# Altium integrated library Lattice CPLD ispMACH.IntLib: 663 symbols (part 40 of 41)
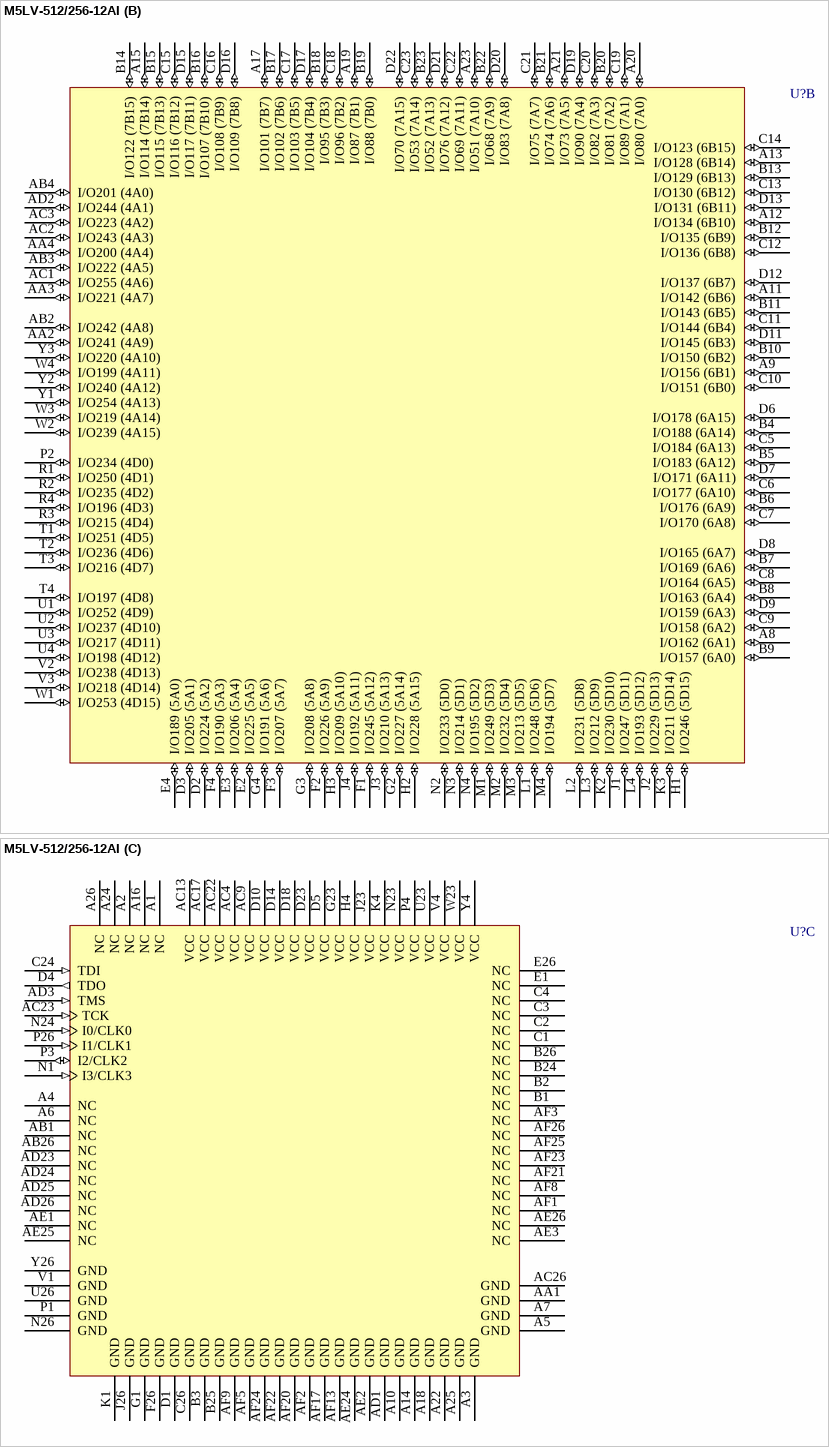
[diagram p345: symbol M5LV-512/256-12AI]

## M5LV-512/256-12AI
designator U?
High-Density and High-I/O Complex PLD
footprint SBGA352 (BGA, 352-Leads, Body 35x35mm, Pitch 1.27mm)
3D model M5LV-SBGA352 (352-Ball Super Ball Grid Array (SBGA352))
part A pins: AA23 I/O65 (1A3) (io), AA24 I/O48 (1A7) (io), AA25 I/O29 (1A9) (io), AA26 I/O10 (1A12) (io), AB23 I/O66 (1A0) (io), AB24 I/O49 (1A4) (io), AB25 I/O30 (1A5) (io), AC5 I/O185 (3A14) (io), AC6 I/O179 (3A10) (io), AC7 I/O172 (3A6) (io), AC8 I/O166 (3A2) (io), AC10 I/O152 (3B3) (io), AC11 I/O146 (3B7) (io), AC12 I/O138 (3B11) (io), AC14 I/O124 (2B11) (io), AC15 I/O118 (2B7) (io), AC16 I/O110 (2B3) (io), AC18 I/O97 (2A3) (io), AC19 I/O91 (2A7) (io), AC20 I/O84 (2A11) (io), AC21 I/O77 (2A15) (io), AC24 I/O50 (1A1) (io), AC25 I/O31 (1A2) (io), AD4 I/O202 (3A15) (io), AD5 I/O186 (3A11) (io), AD6 I/O180 (3A8) (io), AD7 I/O173 (3A4) (io), AD8 I/O167 (3A1) (io), AD9 I/O160 (3B1) (io), AD10 I/O153 (3B4) (io), AD11 I/O147 (3B8) (io), AD12 I/O139 (3B12) (io), AD13 I/O132 (2B15) (io), AD14 I/O125 (2B12) (io), AD15 I/O119 (2B8) (io), AD16 I/O111 (2B4) (io), AD17 I/O105 (2B0) (io), AD18 I/O98 (2A2) (io), AD19 I/O92 (2A5) (io), AD20 I/O85 (2A8) (io), AD21 I/O78 (2A10) (io), AD22 I/O71 (2A13) (io), AE4 I/O203 (3A13) (io), AE5 I/O187 (3A9) (io), AE6 I/O181 (3A7) (io), AE7 I/O174 (3A3) (io), AE8 I/O168 (3B0) (io), AE9 I/O161 (3B2) (io), AE10 I/O154 (3B5) (io), AE11 I/O148 (3B9) (io), AE12 I/O140 (3B13) (io), AE13 I/O133 (3B15) (io), AE14 I/O126 (2B13) (io), AE15 I/O120 (2B9) (io), AE16 I/O112 (2B5) (io), AE17 I/O106 (2B2) (io), AE18 I/O99 (2A0) (io), AE19 I/O93 (2A4) (io), AE20 I/O86 (2A6) (io), AE21 I/O79 (2A9) (io), AE22 I/O72 (2A12) (io), AE23 I/O67 (2A14) (io), AF4 I/O204 (3A12) (io), AF6 I/O182 (3A5) (io), AF7 I/O175 (3A0) (io), AF10 I/O155 (3B6) (io), AF11 I/O149 (3B10) (io), AF12 I/O141 (3B14) (io), AF14 I/O127 (2B14) (io), AF15 I/O121 (2B10) (io), AF16 I/O113 (2B6) (io), AF18 I/O100 (2B1) (io), AF19 I/O94 (2A1) (io), C25 I/O11 (0A1) (io), D24 I/O32 (0A2) (io), D25 I/O12 (0A3) (io), D26 I/O0 (0A6) (io), E23 I/O54 (0A0) (io), E24 I/O33 (0A5) (io), E25 I/O13 (0A8) (io), F23 I/O55 (0A4) (io), F24 I/O34 (0A7) (io), F25 I/O14 (0A9) (io), G24 I/O35 (0A10) (io), G25 I/O15 (0A12) (io), G26 I/O1 (0A13) (io), H23 I/O56 (0A11) (io), H24 I/O36 (0A14) (io), H25 I/O16 (0A15) (io), H26 I/O2 (0D15) (io), J24 I/O37 (0D14) (io), J25 I/O17 (0D13) (io), K23 I/O57 (0D12) (io), K24 I/O38 (0D11) (io), K25 I/O18 (0D10) (io), K26 I/O3 (0D9) (io), L23 I/O58 (0D8) (io), L24 I/O39 (0D7) (io), L25 I/O19 (0D6) (io), L26 I/O4 (0D5) (io), M23 I/O59 (0D3) (io), M24 I/O40 (0D4) (io), M25 I/O20 (0D2) (io), M26 I/O5 (0D1) (io), N25 I/O21 (0D0) (io), P23 I/O60 (1D2) (io), P24 I/O41 (1D1) (io), P25 I/O22 (1D0) (io), R23 I/O61 (1D7) (io), R24 I/O42 (1D5) (io), R25 I/O23 (1D4) (io), R26 I/O6 (1D3) (io), T23 I/O62 (1D12) (io), T24 I/O43 (1D9) (io), T25 I/O24 (1D8) (io), T26 I/O7 (1D6) (io), U24 I/O44 (1D14) (io), U25 I/O25 (1D10) (io), V23 I/O63 (1A11) (io), V24 I/O45 (1A13) (io), V25 I/O26 (1D13) (io), V26 I/O8 (1D11) (io), W24 I/O46 (1A10) (io), W25 I/O27 (1A15) (io), W26 I/O9 (1D15) (io), Y23 I/O64 (1A6) (io), Y24 I/O47 (1A8) (io), Y25 I/O28 (1A14) (io)
part B pins: A8 I/O162 (6A1) (io), A9 I/O156 (6B1) (io), A11 I/O142 (6B6) (io), A12 I/O134 (6B10) (io), A13 I/O128 (6B14) (io), A15 I/O114 (7B14) (io), A17 I/O101 (7B7) (io), A19 I/O87 (7B1) (io), A20 I/O80 (7A0) (io), A21 I/O73 (7A5) (io), A23 I/O51 (7A10) (io), AA2 I/O241 (4A9) (io), AA3 I/O221 (4A7) (io), AA4 I/O200 (4A4) (io), AB2 I/O242 (4A8) (io), AB3 I/O222 (4A5) (io), AB4 I/O201 (4A0) (io), AC1 I/O255 (4A6) (io), AC2 I/O243 (4A3) (io), AC3 I/O223 (4A2) (io), AD2 I/O244 (4A1) (io), B4 I/O188 (6A14) (io), B5 I/O183 (6A12) (io), B6 I/O176 (6A9) (io), B7 I/O169 (6A6) (io), B8 I/O163 (6A4) (io), B9 I/O157 (6A0) (io), B10 I/O150 (6B2) (io), B11 I/O143 (6B5) (io), B12 I/O135 (6B9) (io), B13 I/O129 (6B13) (io), B14 I/O122 (7B15) (io), B15 I/O115 (7B13) (io), B16 I/O107 (7B10) (io), B17 I/O102 (7B6) (io), B18 I/O95 (7B3) (io), B19 I/O88 (7B0) (io), B20 I/O81 (7A2) (io), B21 I/O74 (7A6) (io), B22 I/O68 (7A9) (io), B23 I/O52 (7A13) (io), C5 I/O184 (6A13) (io), C6 I/O177 (6A10) (io), C7 I/O170 (6A8) (io), C8 I/O164 (6A5) (io), C9 I/O158 (6A2) (io), C10 I/O151 (6B0) (io), C11 I/O144 (6B4) (io), C12 I/O136 (6B8) (io), C13 I/O130 (6B12) (io), C14 I/O123 (6B15) (io), C15 I/O116 (7B12) (io), C16 I/O108 (7B9) (io), C17 I/O103 (7B5) (io), C18 I/O96 (7B2) (io), C19 I/O89 (7A1) (io), C20 I/O82 (7A3) (io), C21 I/O75 (7A7) (io), C22 I/O69 (7A11) (io), C23 I/O53 (7A14) (io), D2 I/O224 (5A2) (io), D3 I/O205 (5A1) (io), D6 I/O178 (6A15) (io), D7 I/O171 (6A11) (io), D8 I/O165 (6A7) (io), D9 I/O159 (6A3) (io), D11 I/O145 (6B3) (io), D12 I/O137 (6B7) (io), D13 I/O131 (6B11) (io), D15 I/O117 (7B11) (io), D16 I/O109 (7B8) (io), D17 I/O104 (7B4) (io), D19 I/O90 (7A4) (io), D20 I/O83 (7A8) (io), D21 I/O76 (7A12) (io), D22 I/O70 (7A15) (io), E2 I/O225 (5A5) (io), E3 I/O206 (5A4) (io), E4 I/O189 (5A0) (io), F1 I/O245 (5A12) (io), F2 I/O226 (5A9) (io), F3 I/O207 (5A7) (io), F4 I/O190 (5A3) (io), G2 I/O227 (5A14) (io), G3 I/O208 (5A8) (io), G4 I/O191 (5A6) (io), H1 I/O246 (5D15) (io), H2 I/O228 (5A15) (io), H3 I/O209 (5A10) (io), J1 I/O247 (5D11) (io), J2 I/O229 (5D13) (io), J3 I/O210 (5A13) (io), J4 I/O192 (5A11) (io), K2 I/O230 (5D10) (io), K3 I/O211 (5D14) (io), L1 I/O248 (5D6) (io), L2 I/O231 (5D8) (io), L3 I/O212 (5D9) (io), L4 I/O193 (5D12) (io), M1 I/O249 (5D3) (io), M2 I/O232 (5D4) (io), M3 I/O213 (5D5) (io), M4 I/O194 (5D7) (io), N2 I/O233 (5D0) (io), N3 I/O214 (5D1) (io), N4 I/O195 (5D2) (io), P2 I/O234 (4D0) (io), R1 I/O250 (4D1) (io), R2 I/O235 (4D2) (io), R3 I/O215 (4D4) (io), R4 I/O196 (4D3) (io), T1 I/O251 (4D5) (io), T2 I/O236 (4D6) (io), T3 I/O216 (4D7) (io), T4 I/O197 (4D8) (io), U1 I/O252 (4D9) (io), U2 I/O237 (4D10) (io), U3 I/O217 (4D11) (io), U4 I/O198 (4D12) (io), V2 I/O238 (4D13) (io), V3 I/O218 (4D14) (io), W1 I/O253 (4D15) (io), W2 I/O239 (4A15) (io), W3 I/O219 (4A14) (io), W4 I/O199 (4A11) (io), Y1 I/O254 (4A13) (io), Y2 I/O240 (4A12) (io), Y3 I/O220 (4A10) (io)
part C pins: A1 NC, A2 NC, A3 GND (power), A4 NC, A5 GND (power), A6 NC, A7 GND (power), A10 GND (power), A14 GND (power), A16 NC, A18 GND (power), A22 GND (power), A24 NC, A25 GND (power), A26 NC, AA1 GND (power), AB1 NC, AB26 NC, AC4 VCC (power), AC9 VCC (power), AC13 VCC (power), AC17 VCC (power), AC22 VCC (power), AC23 TCK (in), AC26 GND (power), AD1 GND (power), AD3 TMS (in), AD23 NC, AD24 NC, AD25 NC, AD26 NC, AE1 NC, AE2 GND (power), AE3 NC, AE24 GND (power), AE25 NC, AE26 NC, AF1 NC, AF2 GND (power), AF3 NC, AF5 GND (power), AF8 NC, AF9 GND (power), AF13 GND (power), AF17 GND (power), AF20 GND (power), AF21 NC, AF22 GND (power), AF23 NC, AF24 GND (power), AF25 NC, AF26 NC, B1 NC, B2 NC, B3 GND (power), B24 NC, B25 GND (power), B26 NC, C1 NC, C2 NC, C3 NC, C4 NC, C24 TDI (in), C26 GND (power), D1 GND (power), D4 TDO (out), D5 VCC (power), D10 VCC (power), D14 VCC (power), D18 VCC (power), D23 VCC (power), E1 NC, E26 NC, F26 GND (power), G1 GND (power), G23 VCC (power), H4 VCC (power), J23 VCC (power), J26 GND (power), K1 GND (power), K4 VCC (power), N1 I3/CLK3 (in), N23 VCC (power), N24 I0/CLK0 (in), N26 GND (power), P1 GND (power), P3 I2/CLK2 (io), P4 VCC (power), P26 I1/CLK1 (in), U23 VCC (power), U26 GND (power), V1 GND (power), V4 VCC (power), W23 VCC (power), Y4 VCC (power), Y26 GND (power)

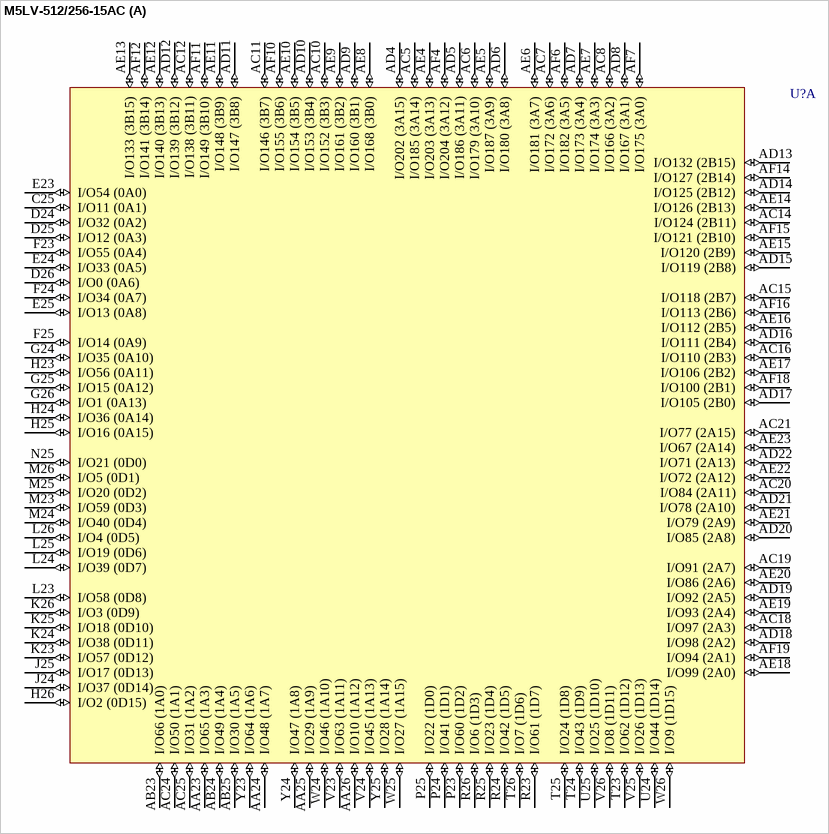
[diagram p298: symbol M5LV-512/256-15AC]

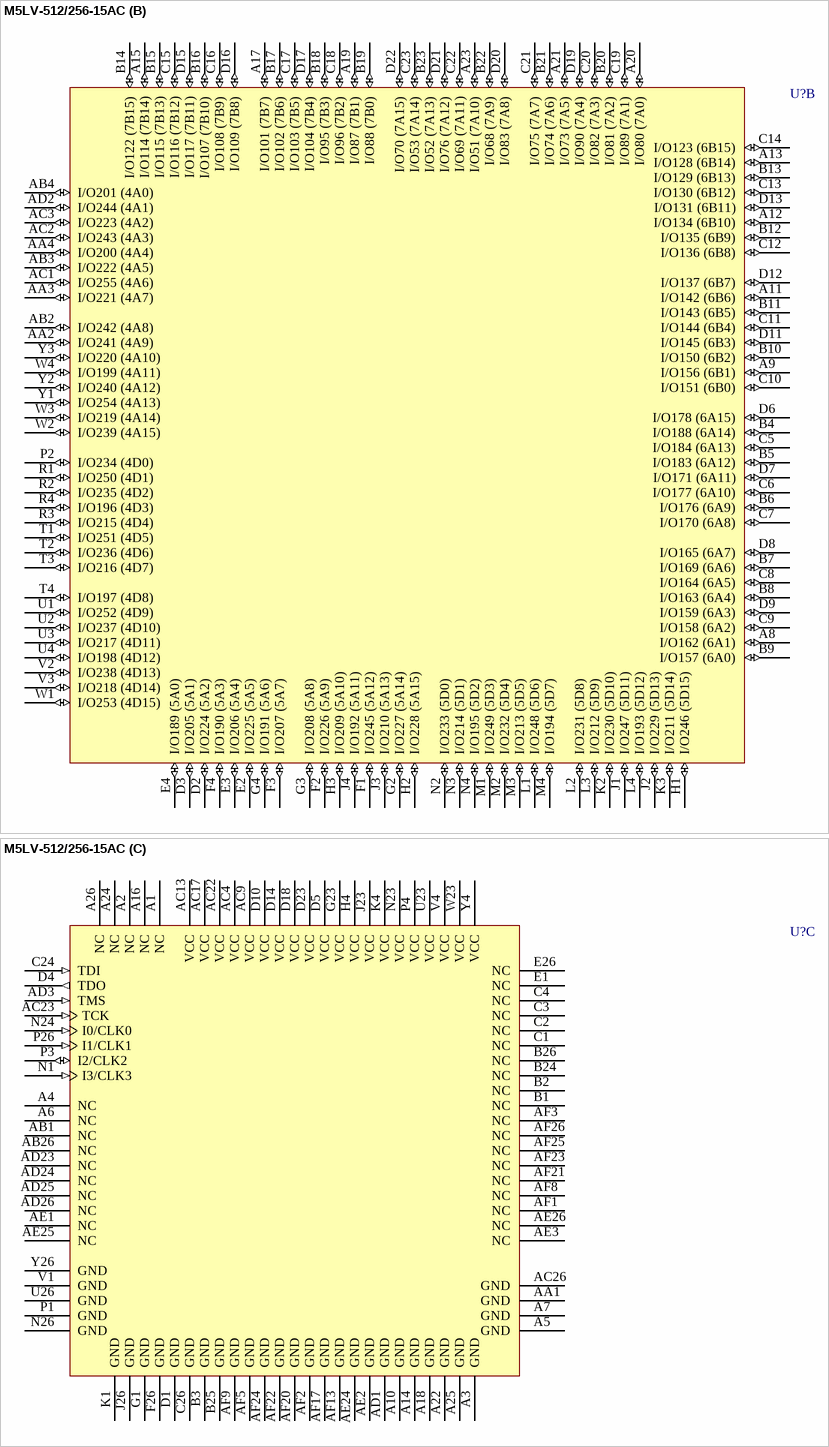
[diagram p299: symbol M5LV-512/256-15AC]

## M5LV-512/256-15AC
designator U?
High-Density and High-I/O Complex PLD
footprint SBGA352 (BGA, 352-Leads, Body 35x35mm, Pitch 1.27mm)
3D model M5LV-SBGA352 (352-Ball Super Ball Grid Array (SBGA352))
part A pins: AA23 I/O65 (1A3) (io), AA24 I/O48 (1A7) (io), AA25 I/O29 (1A9) (io), AA26 I/O10 (1A12) (io), AB23 I/O66 (1A0) (io), AB24 I/O49 (1A4) (io), AB25 I/O30 (1A5) (io), AC5 I/O185 (3A14) (io), AC6 I/O179 (3A10) (io), AC7 I/O172 (3A6) (io), AC8 I/O166 (3A2) (io), AC10 I/O152 (3B3) (io), AC11 I/O146 (3B7) (io), AC12 I/O138 (3B11) (io), AC14 I/O124 (2B11) (io), AC15 I/O118 (2B7) (io), AC16 I/O110 (2B3) (io), AC18 I/O97 (2A3) (io), AC19 I/O91 (2A7) (io), AC20 I/O84 (2A11) (io), AC21 I/O77 (2A15) (io), AC24 I/O50 (1A1) (io), AC25 I/O31 (1A2) (io), AD4 I/O202 (3A15) (io), AD5 I/O186 (3A11) (io), AD6 I/O180 (3A8) (io), AD7 I/O173 (3A4) (io), AD8 I/O167 (3A1) (io), AD9 I/O160 (3B1) (io), AD10 I/O153 (3B4) (io), AD11 I/O147 (3B8) (io), AD12 I/O139 (3B12) (io), AD13 I/O132 (2B15) (io), AD14 I/O125 (2B12) (io), AD15 I/O119 (2B8) (io), AD16 I/O111 (2B4) (io), AD17 I/O105 (2B0) (io), AD18 I/O98 (2A2) (io), AD19 I/O92 (2A5) (io), AD20 I/O85 (2A8) (io), AD21 I/O78 (2A10) (io), AD22 I/O71 (2A13) (io), AE4 I/O203 (3A13) (io), AE5 I/O187 (3A9) (io), AE6 I/O181 (3A7) (io), AE7 I/O174 (3A3) (io), AE8 I/O168 (3B0) (io), AE9 I/O161 (3B2) (io), AE10 I/O154 (3B5) (io), AE11 I/O148 (3B9) (io), AE12 I/O140 (3B13) (io), AE13 I/O133 (3B15) (io), AE14 I/O126 (2B13) (io), AE15 I/O120 (2B9) (io), AE16 I/O112 (2B5) (io), AE17 I/O106 (2B2) (io), AE18 I/O99 (2A0) (io), AE19 I/O93 (2A4) (io), AE20 I/O86 (2A6) (io), AE21 I/O79 (2A9) (io), AE22 I/O72 (2A12) (io), AE23 I/O67 (2A14) (io), AF4 I/O204 (3A12) (io), AF6 I/O182 (3A5) (io), AF7 I/O175 (3A0) (io), AF10 I/O155 (3B6) (io), AF11 I/O149 (3B10) (io), AF12 I/O141 (3B14) (io), AF14 I/O127 (2B14) (io), AF15 I/O121 (2B10) (io), AF16 I/O113 (2B6) (io), AF18 I/O100 (2B1) (io), AF19 I/O94 (2A1) (io), C25 I/O11 (0A1) (io), D24 I/O32 (0A2) (io), D25 I/O12 (0A3) (io), D26 I/O0 (0A6) (io), E23 I/O54 (0A0) (io), E24 I/O33 (0A5) (io), E25 I/O13 (0A8) (io), F23 I/O55 (0A4) (io), F24 I/O34 (0A7) (io), F25 I/O14 (0A9) (io), G24 I/O35 (0A10) (io), G25 I/O15 (0A12) (io), G26 I/O1 (0A13) (io), H23 I/O56 (0A11) (io), H24 I/O36 (0A14) (io), H25 I/O16 (0A15) (io), H26 I/O2 (0D15) (io), J24 I/O37 (0D14) (io), J25 I/O17 (0D13) (io), K23 I/O57 (0D12) (io), K24 I/O38 (0D11) (io), K25 I/O18 (0D10) (io), K26 I/O3 (0D9) (io), L23 I/O58 (0D8) (io), L24 I/O39 (0D7) (io), L25 I/O19 (0D6) (io), L26 I/O4 (0D5) (io), M23 I/O59 (0D3) (io), M24 I/O40 (0D4) (io), M25 I/O20 (0D2) (io), M26 I/O5 (0D1) (io), N25 I/O21 (0D0) (io), P23 I/O60 (1D2) (io), P24 I/O41 (1D1) (io), P25 I/O22 (1D0) (io), R23 I/O61 (1D7) (io), R24 I/O42 (1D5) (io), R25 I/O23 (1D4) (io), R26 I/O6 (1D3) (io), T23 I/O62 (1D12) (io), T24 I/O43 (1D9) (io), T25 I/O24 (1D8) (io), T26 I/O7 (1D6) (io), U24 I/O44 (1D14) (io), U25 I/O25 (1D10) (io), V23 I/O63 (1A11) (io), V24 I/O45 (1A13) (io), V25 I/O26 (1D13) (io), V26 I/O8 (1D11) (io), W24 I/O46 (1A10) (io), W25 I/O27 (1A15) (io), W26 I/O9 (1D15) (io), Y23 I/O64 (1A6) (io), Y24 I/O47 (1A8) (io), Y25 I/O28 (1A14) (io)
part B pins: A8 I/O162 (6A1) (io), A9 I/O156 (6B1) (io), A11 I/O142 (6B6) (io), A12 I/O134 (6B10) (io), A13 I/O128 (6B14) (io), A15 I/O114 (7B14) (io), A17 I/O101 (7B7) (io), A19 I/O87 (7B1) (io), A20 I/O80 (7A0) (io), A21 I/O73 (7A5) (io), A23 I/O51 (7A10) (io), AA2 I/O241 (4A9) (io), AA3 I/O221 (4A7) (io), AA4 I/O200 (4A4) (io), AB2 I/O242 (4A8) (io), AB3 I/O222 (4A5) (io), AB4 I/O201 (4A0) (io), AC1 I/O255 (4A6) (io), AC2 I/O243 (4A3) (io), AC3 I/O223 (4A2) (io), AD2 I/O244 (4A1) (io), B4 I/O188 (6A14) (io), B5 I/O183 (6A12) (io), B6 I/O176 (6A9) (io), B7 I/O169 (6A6) (io), B8 I/O163 (6A4) (io), B9 I/O157 (6A0) (io), B10 I/O150 (6B2) (io), B11 I/O143 (6B5) (io), B12 I/O135 (6B9) (io), B13 I/O129 (6B13) (io), B14 I/O122 (7B15) (io), B15 I/O115 (7B13) (io), B16 I/O107 (7B10) (io), B17 I/O102 (7B6) (io), B18 I/O95 (7B3) (io), B19 I/O88 (7B0) (io), B20 I/O81 (7A2) (io), B21 I/O74 (7A6) (io), B22 I/O68 (7A9) (io), B23 I/O52 (7A13) (io), C5 I/O184 (6A13) (io), C6 I/O177 (6A10) (io), C7 I/O170 (6A8) (io), C8 I/O164 (6A5) (io), C9 I/O158 (6A2) (io), C10 I/O151 (6B0) (io), C11 I/O144 (6B4) (io), C12 I/O136 (6B8) (io), C13 I/O130 (6B12) (io), C14 I/O123 (6B15) (io), C15 I/O116 (7B12) (io), C16 I/O108 (7B9) (io), C17 I/O103 (7B5) (io), C18 I/O96 (7B2) (io), C19 I/O89 (7A1) (io), C20 I/O82 (7A3) (io), C21 I/O75 (7A7) (io), C22 I/O69 (7A11) (io), C23 I/O53 (7A14) (io), D2 I/O224 (5A2) (io), D3 I/O205 (5A1) (io), D6 I/O178 (6A15) (io), D7 I/O171 (6A11) (io), D8 I/O165 (6A7) (io), D9 I/O159 (6A3) (io), D11 I/O145 (6B3) (io), D12 I/O137 (6B7) (io), D13 I/O131 (6B11) (io), D15 I/O117 (7B11) (io), D16 I/O109 (7B8) (io), D17 I/O104 (7B4) (io), D19 I/O90 (7A4) (io), D20 I/O83 (7A8) (io), D21 I/O76 (7A12) (io), D22 I/O70 (7A15) (io), E2 I/O225 (5A5) (io), E3 I/O206 (5A4) (io), E4 I/O189 (5A0) (io), F1 I/O245 (5A12) (io), F2 I/O226 (5A9) (io), F3 I/O207 (5A7) (io), F4 I/O190 (5A3) (io), G2 I/O227 (5A14) (io), G3 I/O208 (5A8) (io), G4 I/O191 (5A6) (io), H1 I/O246 (5D15) (io), H2 I/O228 (5A15) (io), H3 I/O209 (5A10) (io), J1 I/O247 (5D11) (io), J2 I/O229 (5D13) (io), J3 I/O210 (5A13) (io), J4 I/O192 (5A11) (io), K2 I/O230 (5D10) (io), K3 I/O211 (5D14) (io), L1 I/O248 (5D6) (io), L2 I/O231 (5D8) (io), L3 I/O212 (5D9) (io), L4 I/O193 (5D12) (io), M1 I/O249 (5D3) (io), M2 I/O232 (5D4) (io), M3 I/O213 (5D5) (io), M4 I/O194 (5D7) (io), N2 I/O233 (5D0) (io), N3 I/O214 (5D1) (io), N4 I/O195 (5D2) (io), P2 I/O234 (4D0) (io), R1 I/O250 (4D1) (io), R2 I/O235 (4D2) (io), R3 I/O215 (4D4) (io), R4 I/O196 (4D3) (io), T1 I/O251 (4D5) (io), T2 I/O236 (4D6) (io), T3 I/O216 (4D7) (io), T4 I/O197 (4D8) (io), U1 I/O252 (4D9) (io), U2 I/O237 (4D10) (io), U3 I/O217 (4D11) (io), U4 I/O198 (4D12) (io), V2 I/O238 (4D13) (io), V3 I/O218 (4D14) (io), W1 I/O253 (4D15) (io), W2 I/O239 (4A15) (io), W3 I/O219 (4A14) (io), W4 I/O199 (4A11) (io), Y1 I/O254 (4A13) (io), Y2 I/O240 (4A12) (io), Y3 I/O220 (4A10) (io)
part C pins: A1 NC, A2 NC, A3 GND (power), A4 NC, A5 GND (power), A6 NC, A7 GND (power), A10 GND (power), A14 GND (power), A16 NC, A18 GND (power), A22 GND (power), A24 NC, A25 GND (power), A26 NC, AA1 GND (power), AB1 NC, AB26 NC, AC4 VCC (power), AC9 VCC (power), AC13 VCC (power), AC17 VCC (power), AC22 VCC (power), AC23 TCK (in), AC26 GND (power), AD1 GND (power), AD3 TMS (in), AD23 NC, AD24 NC, AD25 NC, AD26 NC, AE1 NC, AE2 GND (power), AE3 NC, AE24 GND (power), AE25 NC, AE26 NC, AF1 NC, AF2 GND (power), AF3 NC, AF5 GND (power), AF8 NC, AF9 GND (power), AF13 GND (power), AF17 GND (power), AF20 GND (power), AF21 NC, AF22 GND (power), AF23 NC, AF24 GND (power), AF25 NC, AF26 NC, B1 NC, B2 NC, B3 GND (power), B24 NC, B25 GND (power), B26 NC, C1 NC, C2 NC, C3 NC, C4 NC, C24 TDI (in), C26 GND (power), D1 GND (power), D4 TDO (out), D5 VCC (power), D10 VCC (power), D14 VCC (power), D18 VCC (power), D23 VCC (power), E1 NC, E26 NC, F26 GND (power), G1 GND (power), G23 VCC (power), H4 VCC (power), J23 VCC (power), J26 GND (power), K1 GND (power), K4 VCC (power), N1 I3/CLK3 (in), N23 VCC (power), N24 I0/CLK0 (in), N26 GND (power), P1 GND (power), P3 I2/CLK2 (io), P4 VCC (power), P26 I1/CLK1 (in), U23 VCC (power), U26 GND (power), V1 GND (power), V4 VCC (power), W23 VCC (power), Y4 VCC (power), Y26 GND (power)

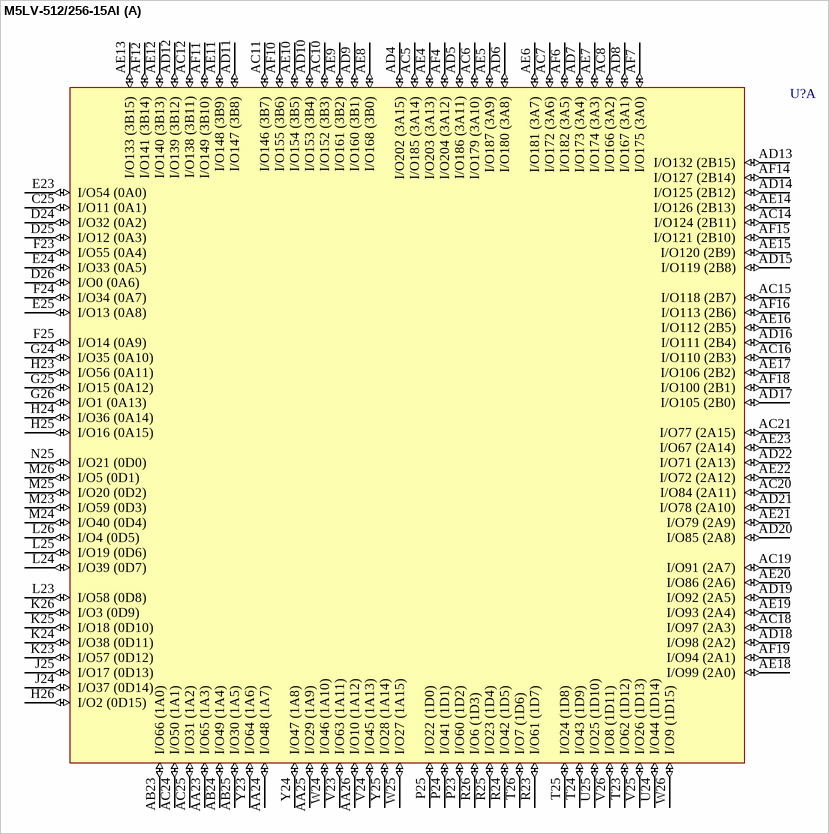
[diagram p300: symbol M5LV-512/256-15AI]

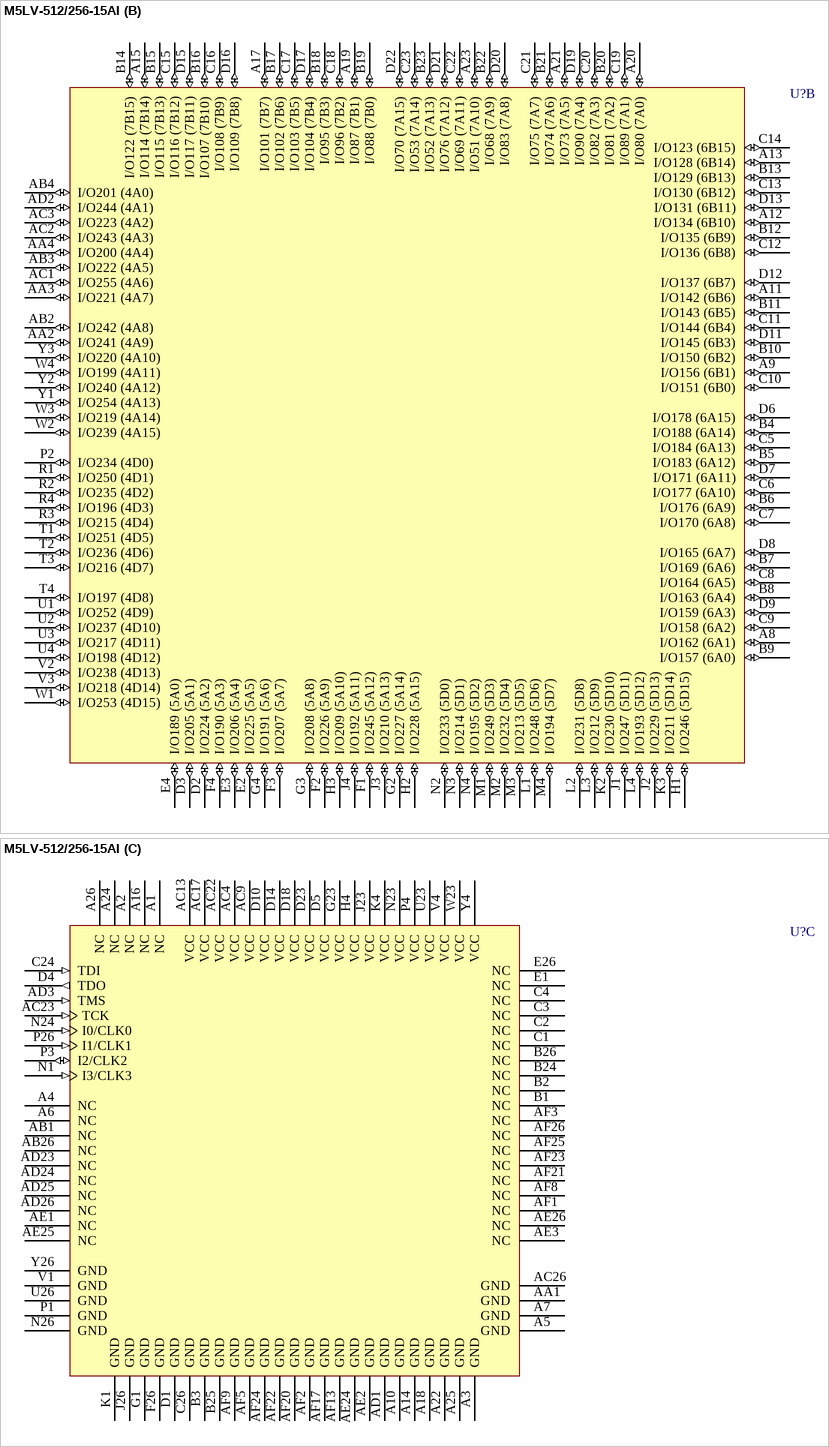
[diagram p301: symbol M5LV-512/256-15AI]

## M5LV-512/256-15AI
designator U?
High-Density and High-I/O Complex PLD
footprint SBGA352 (BGA, 352-Leads, Body 35x35mm, Pitch 1.27mm)
3D model M5LV-SBGA352 (352-Ball Super Ball Grid Array (SBGA352))
part A pins: AA23 I/O65 (1A3) (io), AA24 I/O48 (1A7) (io), AA25 I/O29 (1A9) (io), AA26 I/O10 (1A12) (io), AB23 I/O66 (1A0) (io), AB24 I/O49 (1A4) (io), AB25 I/O30 (1A5) (io), AC5 I/O185 (3A14) (io), AC6 I/O179 (3A10) (io), AC7 I/O172 (3A6) (io), AC8 I/O166 (3A2) (io), AC10 I/O152 (3B3) (io), AC11 I/O146 (3B7) (io), AC12 I/O138 (3B11) (io), AC14 I/O124 (2B11) (io), AC15 I/O118 (2B7) (io), AC16 I/O110 (2B3) (io), AC18 I/O97 (2A3) (io), AC19 I/O91 (2A7) (io), AC20 I/O84 (2A11) (io), AC21 I/O77 (2A15) (io), AC24 I/O50 (1A1) (io), AC25 I/O31 (1A2) (io), AD4 I/O202 (3A15) (io), AD5 I/O186 (3A11) (io), AD6 I/O180 (3A8) (io), AD7 I/O173 (3A4) (io), AD8 I/O167 (3A1) (io), AD9 I/O160 (3B1) (io), AD10 I/O153 (3B4) (io), AD11 I/O147 (3B8) (io), AD12 I/O139 (3B12) (io), AD13 I/O132 (2B15) (io), AD14 I/O125 (2B12) (io), AD15 I/O119 (2B8) (io), AD16 I/O111 (2B4) (io), AD17 I/O105 (2B0) (io), AD18 I/O98 (2A2) (io), AD19 I/O92 (2A5) (io), AD20 I/O85 (2A8) (io), AD21 I/O78 (2A10) (io), AD22 I/O71 (2A13) (io), AE4 I/O203 (3A13) (io), AE5 I/O187 (3A9) (io), AE6 I/O181 (3A7) (io), AE7 I/O174 (3A3) (io), AE8 I/O168 (3B0) (io), AE9 I/O161 (3B2) (io), AE10 I/O154 (3B5) (io), AE11 I/O148 (3B9) (io), AE12 I/O140 (3B13) (io), AE13 I/O133 (3B15) (io), AE14 I/O126 (2B13) (io), AE15 I/O120 (2B9) (io), AE16 I/O112 (2B5) (io), AE17 I/O106 (2B2) (io), AE18 I/O99 (2A0) (io), AE19 I/O93 (2A4) (io), AE20 I/O86 (2A6) (io), AE21 I/O79 (2A9) (io), AE22 I/O72 (2A12) (io), AE23 I/O67 (2A14) (io), AF4 I/O204 (3A12) (io), AF6 I/O182 (3A5) (io), AF7 I/O175 (3A0) (io), AF10 I/O155 (3B6) (io), AF11 I/O149 (3B10) (io), AF12 I/O141 (3B14) (io), AF14 I/O127 (2B14) (io), AF15 I/O121 (2B10) (io), AF16 I/O113 (2B6) (io), AF18 I/O100 (2B1) (io), AF19 I/O94 (2A1) (io), C25 I/O11 (0A1) (io), D24 I/O32 (0A2) (io), D25 I/O12 (0A3) (io), D26 I/O0 (0A6) (io), E23 I/O54 (0A0) (io), E24 I/O33 (0A5) (io), E25 I/O13 (0A8) (io), F23 I/O55 (0A4) (io), F24 I/O34 (0A7) (io), F25 I/O14 (0A9) (io), G24 I/O35 (0A10) (io), G25 I/O15 (0A12) (io), G26 I/O1 (0A13) (io), H23 I/O56 (0A11) (io), H24 I/O36 (0A14) (io), H25 I/O16 (0A15) (io), H26 I/O2 (0D15) (io), J24 I/O37 (0D14) (io), J25 I/O17 (0D13) (io), K23 I/O57 (0D12) (io), K24 I/O38 (0D11) (io), K25 I/O18 (0D10) (io), K26 I/O3 (0D9) (io), L23 I/O58 (0D8) (io), L24 I/O39 (0D7) (io), L25 I/O19 (0D6) (io), L26 I/O4 (0D5) (io), M23 I/O59 (0D3) (io), M24 I/O40 (0D4) (io), M25 I/O20 (0D2) (io), M26 I/O5 (0D1) (io), N25 I/O21 (0D0) (io), P23 I/O60 (1D2) (io), P24 I/O41 (1D1) (io), P25 I/O22 (1D0) (io), R23 I/O61 (1D7) (io), R24 I/O42 (1D5) (io), R25 I/O23 (1D4) (io), R26 I/O6 (1D3) (io), T23 I/O62 (1D12) (io), T24 I/O43 (1D9) (io), T25 I/O24 (1D8) (io), T26 I/O7 (1D6) (io), U24 I/O44 (1D14) (io), U25 I/O25 (1D10) (io), V23 I/O63 (1A11) (io), V24 I/O45 (1A13) (io), V25 I/O26 (1D13) (io), V26 I/O8 (1D11) (io), W24 I/O46 (1A10) (io), W25 I/O27 (1A15) (io), W26 I/O9 (1D15) (io), Y23 I/O64 (1A6) (io), Y24 I/O47 (1A8) (io), Y25 I/O28 (1A14) (io)
part B pins: A8 I/O162 (6A1) (io), A9 I/O156 (6B1) (io), A11 I/O142 (6B6) (io), A12 I/O134 (6B10) (io), A13 I/O128 (6B14) (io), A15 I/O114 (7B14) (io), A17 I/O101 (7B7) (io), A19 I/O87 (7B1) (io), A20 I/O80 (7A0) (io), A21 I/O73 (7A5) (io), A23 I/O51 (7A10) (io), AA2 I/O241 (4A9) (io), AA3 I/O221 (4A7) (io), AA4 I/O200 (4A4) (io), AB2 I/O242 (4A8) (io), AB3 I/O222 (4A5) (io), AB4 I/O201 (4A0) (io), AC1 I/O255 (4A6) (io), AC2 I/O243 (4A3) (io), AC3 I/O223 (4A2) (io), AD2 I/O244 (4A1) (io), B4 I/O188 (6A14) (io), B5 I/O183 (6A12) (io), B6 I/O176 (6A9) (io), B7 I/O169 (6A6) (io), B8 I/O163 (6A4) (io), B9 I/O157 (6A0) (io), B10 I/O150 (6B2) (io), B11 I/O143 (6B5) (io), B12 I/O135 (6B9) (io), B13 I/O129 (6B13) (io), B14 I/O122 (7B15) (io), B15 I/O115 (7B13) (io), B16 I/O107 (7B10) (io), B17 I/O102 (7B6) (io), B18 I/O95 (7B3) (io), B19 I/O88 (7B0) (io), B20 I/O81 (7A2) (io), B21 I/O74 (7A6) (io), B22 I/O68 (7A9) (io), B23 I/O52 (7A13) (io), C5 I/O184 (6A13) (io), C6 I/O177 (6A10) (io), C7 I/O170 (6A8) (io), C8 I/O164 (6A5) (io), C9 I/O158 (6A2) (io), C10 I/O151 (6B0) (io), C11 I/O144 (6B4) (io), C12 I/O136 (6B8) (io), C13 I/O130 (6B12) (io), C14 I/O123 (6B15) (io), C15 I/O116 (7B12) (io), C16 I/O108 (7B9) (io), C17 I/O103 (7B5) (io), C18 I/O96 (7B2) (io), C19 I/O89 (7A1) (io), C20 I/O82 (7A3) (io), C21 I/O75 (7A7) (io), C22 I/O69 (7A11) (io), C23 I/O53 (7A14) (io), D2 I/O224 (5A2) (io), D3 I/O205 (5A1) (io), D6 I/O178 (6A15) (io), D7 I/O171 (6A11) (io), D8 I/O165 (6A7) (io), D9 I/O159 (6A3) (io), D11 I/O145 (6B3) (io), D12 I/O137 (6B7) (io), D13 I/O131 (6B11) (io), D15 I/O117 (7B11) (io), D16 I/O109 (7B8) (io), D17 I/O104 (7B4) (io), D19 I/O90 (7A4) (io), D20 I/O83 (7A8) (io), D21 I/O76 (7A12) (io), D22 I/O70 (7A15) (io), E2 I/O225 (5A5) (io), E3 I/O206 (5A4) (io), E4 I/O189 (5A0) (io), F1 I/O245 (5A12) (io), F2 I/O226 (5A9) (io), F3 I/O207 (5A7) (io), F4 I/O190 (5A3) (io), G2 I/O227 (5A14) (io), G3 I/O208 (5A8) (io), G4 I/O191 (5A6) (io), H1 I/O246 (5D15) (io), H2 I/O228 (5A15) (io), H3 I/O209 (5A10) (io), J1 I/O247 (5D11) (io), J2 I/O229 (5D13) (io), J3 I/O210 (5A13) (io), J4 I/O192 (5A11) (io), K2 I/O230 (5D10) (io), K3 I/O211 (5D14) (io), L1 I/O248 (5D6) (io), L2 I/O231 (5D8) (io), L3 I/O212 (5D9) (io), L4 I/O193 (5D12) (io), M1 I/O249 (5D3) (io), M2 I/O232 (5D4) (io), M3 I/O213 (5D5) (io), M4 I/O194 (5D7) (io), N2 I/O233 (5D0) (io), N3 I/O214 (5D1) (io), N4 I/O195 (5D2) (io), P2 I/O234 (4D0) (io), R1 I/O250 (4D1) (io), R2 I/O235 (4D2) (io), R3 I/O215 (4D4) (io), R4 I/O196 (4D3) (io), T1 I/O251 (4D5) (io), T2 I/O236 (4D6) (io), T3 I/O216 (4D7) (io), T4 I/O197 (4D8) (io), U1 I/O252 (4D9) (io), U2 I/O237 (4D10) (io), U3 I/O217 (4D11) (io), U4 I/O198 (4D12) (io), V2 I/O238 (4D13) (io), V3 I/O218 (4D14) (io), W1 I/O253 (4D15) (io), W2 I/O239 (4A15) (io), W3 I/O219 (4A14) (io), W4 I/O199 (4A11) (io), Y1 I/O254 (4A13) (io), Y2 I/O240 (4A12) (io), Y3 I/O220 (4A10) (io)
part C pins: A1 NC, A2 NC, A3 GND (power), A4 NC, A5 GND (power), A6 NC, A7 GND (power), A10 GND (power), A14 GND (power), A16 NC, A18 GND (power), A22 GND (power), A24 NC, A25 GND (power), A26 NC, AA1 GND (power), AB1 NC, AB26 NC, AC4 VCC (power), AC9 VCC (power), AC13 VCC (power), AC17 VCC (power), AC22 VCC (power), AC23 TCK (in), AC26 GND (power), AD1 GND (power), AD3 TMS (in), AD23 NC, AD24 NC, AD25 NC, AD26 NC, AE1 NC, AE2 GND (power), AE3 NC, AE24 GND (power), AE25 NC, AE26 NC, AF1 NC, AF2 GND (power), AF3 NC, AF5 GND (power), AF8 NC, AF9 GND (power), AF13 GND (power), AF17 GND (power), AF20 GND (power), AF21 NC, AF22 GND (power), AF23 NC, AF24 GND (power), AF25 NC, AF26 NC, B1 NC, B2 NC, B3 GND (power), B24 NC, B25 GND (power), B26 NC, C1 NC, C2 NC, C3 NC, C4 NC, C24 TDI (in), C26 GND (power), D1 GND (power), D4 TDO (out), D5 VCC (power), D10 VCC (power), D14 VCC (power), D18 VCC (power), D23 VCC (power), E1 NC, E26 NC, F26 GND (power), G1 GND (power), G23 VCC (power), H4 VCC (power), J23 VCC (power), J26 GND (power), K1 GND (power), K4 VCC (power), N1 I3/CLK3 (in), N23 VCC (power), N24 I0/CLK0 (in), N26 GND (power), P1 GND (power), P3 I2/CLK2 (io), P4 VCC (power), P26 I1/CLK1 (in), U23 VCC (power), U26 GND (power), V1 GND (power), V4 VCC (power), W23 VCC (power), Y4 VCC (power), Y26 GND (power)

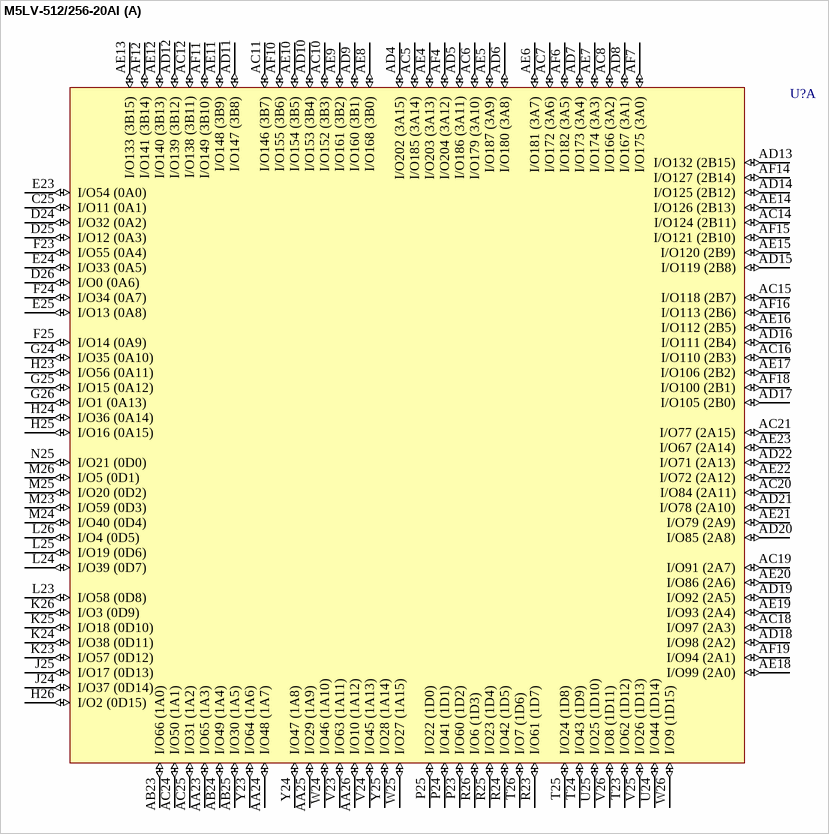
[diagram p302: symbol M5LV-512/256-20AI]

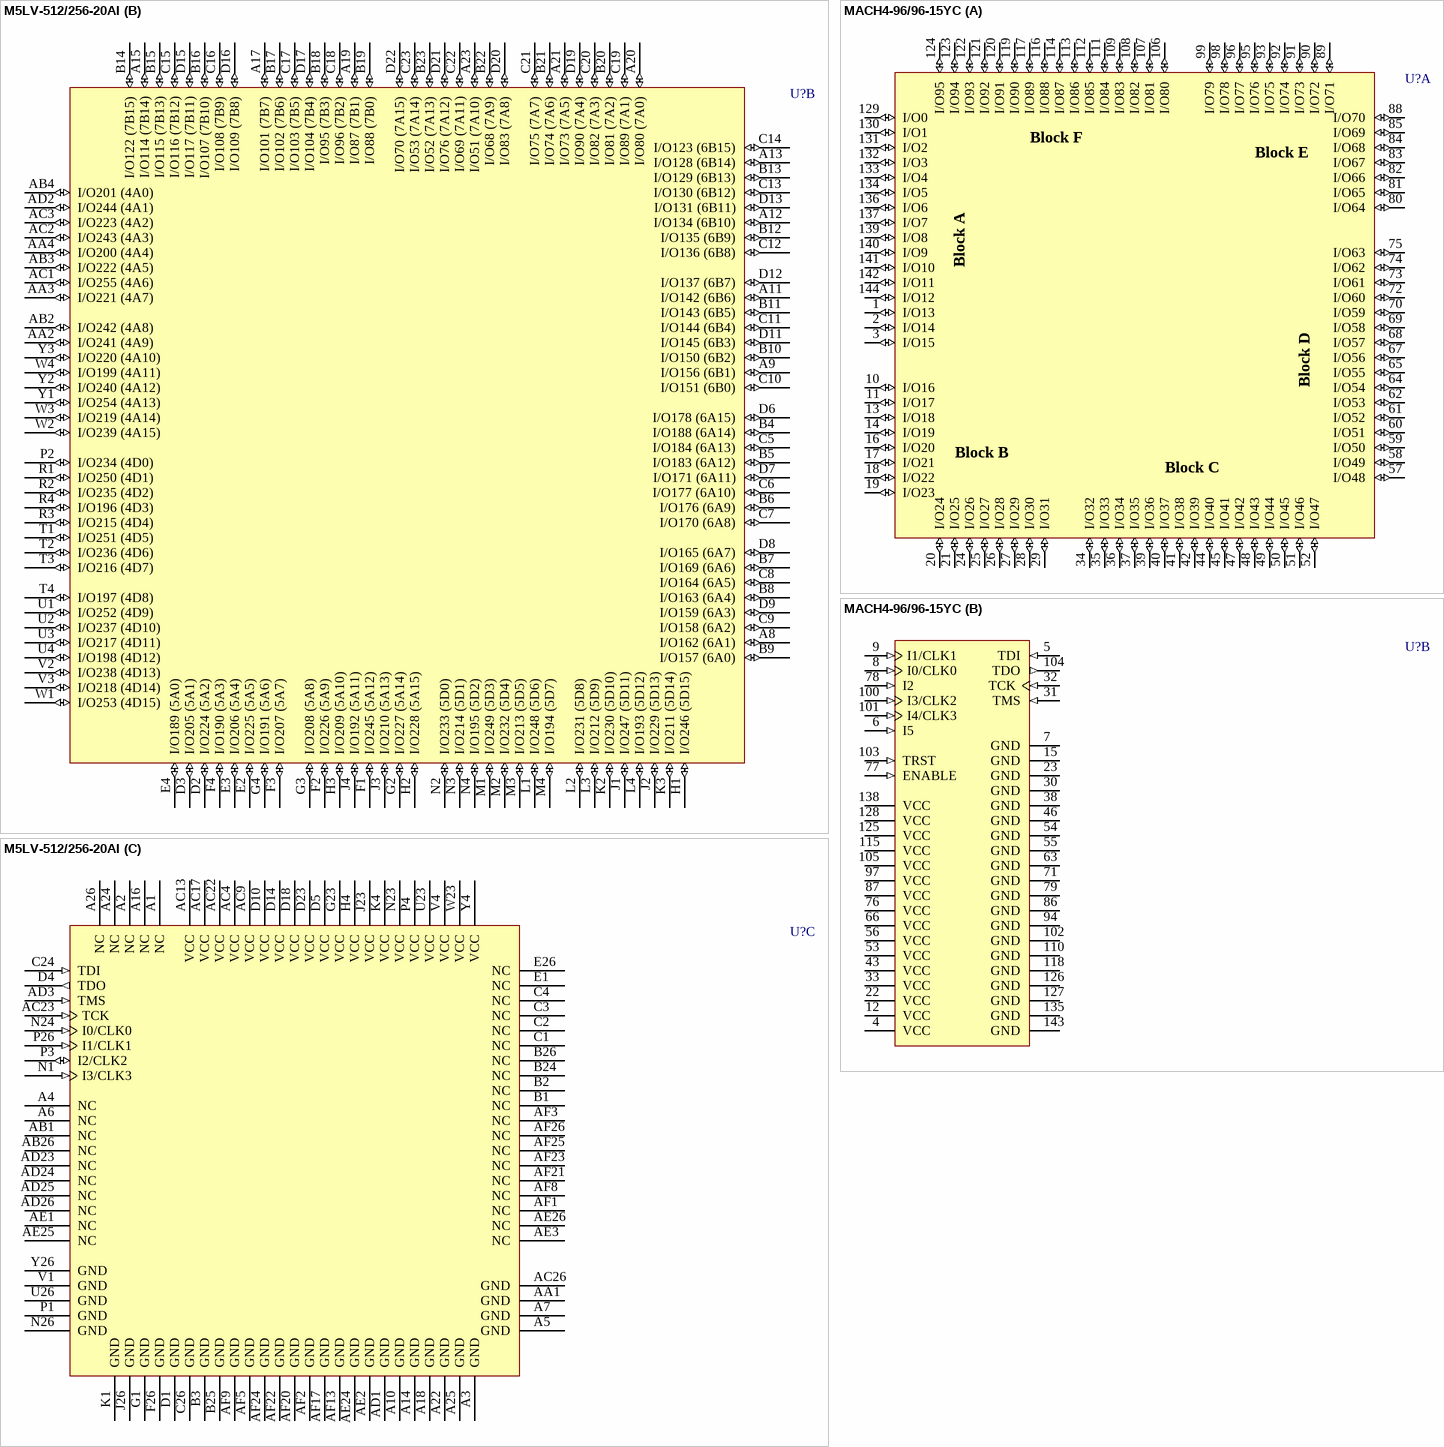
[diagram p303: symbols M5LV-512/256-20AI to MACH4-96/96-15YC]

## M5LV-512/256-20AI
designator U?
High-Density and High-I/O Complex PLD
footprint SBGA352 (BGA, 352-Leads, Body 35x35mm, Pitch 1.27mm)
3D model M5LV-SBGA352 (352-Ball Super Ball Grid Array (SBGA352))
part A pins: AA23 I/O65 (1A3) (io), AA24 I/O48 (1A7) (io), AA25 I/O29 (1A9) (io), AA26 I/O10 (1A12) (io), AB23 I/O66 (1A0) (io), AB24 I/O49 (1A4) (io), AB25 I/O30 (1A5) (io), AC5 I/O185 (3A14) (io), AC6 I/O179 (3A10) (io), AC7 I/O172 (3A6) (io), AC8 I/O166 (3A2) (io), AC10 I/O152 (3B3) (io), AC11 I/O146 (3B7) (io), AC12 I/O138 (3B11) (io), AC14 I/O124 (2B11) (io), AC15 I/O118 (2B7) (io), AC16 I/O110 (2B3) (io), AC18 I/O97 (2A3) (io), AC19 I/O91 (2A7) (io), AC20 I/O84 (2A11) (io), AC21 I/O77 (2A15) (io), AC24 I/O50 (1A1) (io), AC25 I/O31 (1A2) (io), AD4 I/O202 (3A15) (io), AD5 I/O186 (3A11) (io), AD6 I/O180 (3A8) (io), AD7 I/O173 (3A4) (io), AD8 I/O167 (3A1) (io), AD9 I/O160 (3B1) (io), AD10 I/O153 (3B4) (io), AD11 I/O147 (3B8) (io), AD12 I/O139 (3B12) (io), AD13 I/O132 (2B15) (io), AD14 I/O125 (2B12) (io), AD15 I/O119 (2B8) (io), AD16 I/O111 (2B4) (io), AD17 I/O105 (2B0) (io), AD18 I/O98 (2A2) (io), AD19 I/O92 (2A5) (io), AD20 I/O85 (2A8) (io), AD21 I/O78 (2A10) (io), AD22 I/O71 (2A13) (io), AE4 I/O203 (3A13) (io), AE5 I/O187 (3A9) (io), AE6 I/O181 (3A7) (io), AE7 I/O174 (3A3) (io), AE8 I/O168 (3B0) (io), AE9 I/O161 (3B2) (io), AE10 I/O154 (3B5) (io), AE11 I/O148 (3B9) (io), AE12 I/O140 (3B13) (io), AE13 I/O133 (3B15) (io), AE14 I/O126 (2B13) (io), AE15 I/O120 (2B9) (io), AE16 I/O112 (2B5) (io), AE17 I/O106 (2B2) (io), AE18 I/O99 (2A0) (io), AE19 I/O93 (2A4) (io), AE20 I/O86 (2A6) (io), AE21 I/O79 (2A9) (io), AE22 I/O72 (2A12) (io), AE23 I/O67 (2A14) (io), AF4 I/O204 (3A12) (io), AF6 I/O182 (3A5) (io), AF7 I/O175 (3A0) (io), AF10 I/O155 (3B6) (io), AF11 I/O149 (3B10) (io), AF12 I/O141 (3B14) (io), AF14 I/O127 (2B14) (io), AF15 I/O121 (2B10) (io), AF16 I/O113 (2B6) (io), AF18 I/O100 (2B1) (io), AF19 I/O94 (2A1) (io), C25 I/O11 (0A1) (io), D24 I/O32 (0A2) (io), D25 I/O12 (0A3) (io), D26 I/O0 (0A6) (io), E23 I/O54 (0A0) (io), E24 I/O33 (0A5) (io), E25 I/O13 (0A8) (io), F23 I/O55 (0A4) (io), F24 I/O34 (0A7) (io), F25 I/O14 (0A9) (io), G24 I/O35 (0A10) (io), G25 I/O15 (0A12) (io), G26 I/O1 (0A13) (io), H23 I/O56 (0A11) (io), H24 I/O36 (0A14) (io), H25 I/O16 (0A15) (io), H26 I/O2 (0D15) (io), J24 I/O37 (0D14) (io), J25 I/O17 (0D13) (io), K23 I/O57 (0D12) (io), K24 I/O38 (0D11) (io), K25 I/O18 (0D10) (io), K26 I/O3 (0D9) (io), L23 I/O58 (0D8) (io), L24 I/O39 (0D7) (io), L25 I/O19 (0D6) (io), L26 I/O4 (0D5) (io), M23 I/O59 (0D3) (io), M24 I/O40 (0D4) (io), M25 I/O20 (0D2) (io), M26 I/O5 (0D1) (io), N25 I/O21 (0D0) (io), P23 I/O60 (1D2) (io), P24 I/O41 (1D1) (io), P25 I/O22 (1D0) (io), R23 I/O61 (1D7) (io), R24 I/O42 (1D5) (io), R25 I/O23 (1D4) (io), R26 I/O6 (1D3) (io), T23 I/O62 (1D12) (io), T24 I/O43 (1D9) (io), T25 I/O24 (1D8) (io), T26 I/O7 (1D6) (io), U24 I/O44 (1D14) (io), U25 I/O25 (1D10) (io), V23 I/O63 (1A11) (io), V24 I/O45 (1A13) (io), V25 I/O26 (1D13) (io), V26 I/O8 (1D11) (io), W24 I/O46 (1A10) (io), W25 I/O27 (1A15) (io), W26 I/O9 (1D15) (io), Y23 I/O64 (1A6) (io), Y24 I/O47 (1A8) (io), Y25 I/O28 (1A14) (io)
part B pins: A8 I/O162 (6A1) (io), A9 I/O156 (6B1) (io), A11 I/O142 (6B6) (io), A12 I/O134 (6B10) (io), A13 I/O128 (6B14) (io), A15 I/O114 (7B14) (io), A17 I/O101 (7B7) (io), A19 I/O87 (7B1) (io), A20 I/O80 (7A0) (io), A21 I/O73 (7A5) (io), A23 I/O51 (7A10) (io), AA2 I/O241 (4A9) (io), AA3 I/O221 (4A7) (io), AA4 I/O200 (4A4) (io), AB2 I/O242 (4A8) (io), AB3 I/O222 (4A5) (io), AB4 I/O201 (4A0) (io), AC1 I/O255 (4A6) (io), AC2 I/O243 (4A3) (io), AC3 I/O223 (4A2) (io), AD2 I/O244 (4A1) (io), B4 I/O188 (6A14) (io), B5 I/O183 (6A12) (io), B6 I/O176 (6A9) (io), B7 I/O169 (6A6) (io), B8 I/O163 (6A4) (io), B9 I/O157 (6A0) (io), B10 I/O150 (6B2) (io), B11 I/O143 (6B5) (io), B12 I/O135 (6B9) (io), B13 I/O129 (6B13) (io), B14 I/O122 (7B15) (io), B15 I/O115 (7B13) (io), B16 I/O107 (7B10) (io), B17 I/O102 (7B6) (io), B18 I/O95 (7B3) (io), B19 I/O88 (7B0) (io), B20 I/O81 (7A2) (io), B21 I/O74 (7A6) (io), B22 I/O68 (7A9) (io), B23 I/O52 (7A13) (io), C5 I/O184 (6A13) (io), C6 I/O177 (6A10) (io), C7 I/O170 (6A8) (io), C8 I/O164 (6A5) (io), C9 I/O158 (6A2) (io), C10 I/O151 (6B0) (io), C11 I/O144 (6B4) (io), C12 I/O136 (6B8) (io), C13 I/O130 (6B12) (io), C14 I/O123 (6B15) (io), C15 I/O116 (7B12) (io), C16 I/O108 (7B9) (io), C17 I/O103 (7B5) (io), C18 I/O96 (7B2) (io), C19 I/O89 (7A1) (io), C20 I/O82 (7A3) (io), C21 I/O75 (7A7) (io), C22 I/O69 (7A11) (io), C23 I/O53 (7A14) (io), D2 I/O224 (5A2) (io), D3 I/O205 (5A1) (io), D6 I/O178 (6A15) (io), D7 I/O171 (6A11) (io), D8 I/O165 (6A7) (io), D9 I/O159 (6A3) (io), D11 I/O145 (6B3) (io), D12 I/O137 (6B7) (io), D13 I/O131 (6B11) (io), D15 I/O117 (7B11) (io), D16 I/O109 (7B8) (io), D17 I/O104 (7B4) (io), D19 I/O90 (7A4) (io), D20 I/O83 (7A8) (io), D21 I/O76 (7A12) (io), D22 I/O70 (7A15) (io), E2 I/O225 (5A5) (io), E3 I/O206 (5A4) (io), E4 I/O189 (5A0) (io), F1 I/O245 (5A12) (io), F2 I/O226 (5A9) (io), F3 I/O207 (5A7) (io), F4 I/O190 (5A3) (io), G2 I/O227 (5A14) (io), G3 I/O208 (5A8) (io), G4 I/O191 (5A6) (io), H1 I/O246 (5D15) (io), H2 I/O228 (5A15) (io), H3 I/O209 (5A10) (io), J1 I/O247 (5D11) (io), J2 I/O229 (5D13) (io), J3 I/O210 (5A13) (io), J4 I/O192 (5A11) (io), K2 I/O230 (5D10) (io), K3 I/O211 (5D14) (io), L1 I/O248 (5D6) (io), L2 I/O231 (5D8) (io), L3 I/O212 (5D9) (io), L4 I/O193 (5D12) (io), M1 I/O249 (5D3) (io), M2 I/O232 (5D4) (io), M3 I/O213 (5D5) (io), M4 I/O194 (5D7) (io), N2 I/O233 (5D0) (io), N3 I/O214 (5D1) (io), N4 I/O195 (5D2) (io), P2 I/O234 (4D0) (io), R1 I/O250 (4D1) (io), R2 I/O235 (4D2) (io), R3 I/O215 (4D4) (io), R4 I/O196 (4D3) (io), T1 I/O251 (4D5) (io), T2 I/O236 (4D6) (io), T3 I/O216 (4D7) (io), T4 I/O197 (4D8) (io), U1 I/O252 (4D9) (io), U2 I/O237 (4D10) (io), U3 I/O217 (4D11) (io), U4 I/O198 (4D12) (io), V2 I/O238 (4D13) (io), V3 I/O218 (4D14) (io), W1 I/O253 (4D15) (io), W2 I/O239 (4A15) (io), W3 I/O219 (4A14) (io), W4 I/O199 (4A11) (io), Y1 I/O254 (4A13) (io), Y2 I/O240 (4A12) (io), Y3 I/O220 (4A10) (io)
part C pins: A1 NC, A2 NC, A3 GND (power), A4 NC, A5 GND (power), A6 NC, A7 GND (power), A10 GND (power), A14 GND (power), A16 NC, A18 GND (power), A22 GND (power), A24 NC, A25 GND (power), A26 NC, AA1 GND (power), AB1 NC, AB26 NC, AC4 VCC (power), AC9 VCC (power), AC13 VCC (power), AC17 VCC (power), AC22 VCC (power), AC23 TCK (in), AC26 GND (power), AD1 GND (power), AD3 TMS (in), AD23 NC, AD24 NC, AD25 NC, AD26 NC, AE1 NC, AE2 GND (power), AE3 NC, AE24 GND (power), AE25 NC, AE26 NC, AF1 NC, AF2 GND (power), AF3 NC, AF5 GND (power), AF8 NC, AF9 GND (power), AF13 GND (power), AF17 GND (power), AF20 GND (power), AF21 NC, AF22 GND (power), AF23 NC, AF24 GND (power), AF25 NC, AF26 NC, B1 NC, B2 NC, B3 GND (power), B24 NC, B25 GND (power), B26 NC, C1 NC, C2 NC, C3 NC, C4 NC, C24 TDI (in), C26 GND (power), D1 GND (power), D4 TDO (out), D5 VCC (power), D10 VCC (power), D14 VCC (power), D18 VCC (power), D23 VCC (power), E1 NC, E26 NC, F26 GND (power), G1 GND (power), G23 VCC (power), H4 VCC (power), J23 VCC (power), J26 GND (power), K1 GND (power), K4 VCC (power), N1 I3/CLK3 (in), N23 VCC (power), N24 I0/CLK0 (in), N26 GND (power), P1 GND (power), P3 I2/CLK2 (io), P4 VCC (power), P26 I1/CLK1 (in), U23 VCC (power), U26 GND (power), V1 GND (power), V4 VCC (power), W23 VCC (power), Y4 VCC (power), Y26 GND (power)

## MACH4-96/96-15YC
designator U?
High-Performance EE CMOS Programmable Logic
footprint PQFP144_N (QFP, 144-Leads, Body 28 x 28mm, Pitch 0.65mm, IPC Medium Density)
footprint PQFP144_L (QFP, 144-Leads, Body 28 x 28mm, Pitch 0.65mm, IPC High Density)
footprint PQFP144_M (QFP, 144-Leads, Body 28 x 28mm, Pitch 0.65mm, IPC Low Density)
3D model MACH4-96-PQFP144 (144-Pin Quad Flat Pack 0.65 mm Pitch)
part A pins: 1 I/O13 (io), 2 I/O14 (io), 3 I/O15 (io), 10 I/O16 (io), 11 I/O17 (io), 13 I/O18 (io), 14 I/O19 (io), 16 I/O20 (io), 17 I/O21 (io), 18 I/O22 (io), 19 I/O23 (io), 20 I/O24 (io), 21 I/O25 (io), 24 I/O26 (io), 25 I/O27 (io), 26 I/O28 (io), 27 I/O29 (io), 28 I/O30 (io), 29 I/O31 (io), 34 I/O32 (io), 35 I/O33 (io), 36 I/O34 (io), 37 I/O35 (io), 39 I/O36 (io), 40 I/O37 (io), 41 I/O38 (io), 42 I/O39 (io), 44 I/O40 (io), 45 I/O41 (io), 47 I/O42 (io), 48 I/O43 (io), 49 I/O44 (io), 50 I/O45 (io), 51 I/O46 (io), 52 I/O47 (io), 57 I/O48 (io), 58 I/O49 (io), 59 I/O50 (io), 60 I/O51 (io), 61 I/O52 (io), 62 I/O53 (io), 64 I/O54 (io), 65 I/O55 (io), 67 I/O56 (io), 68 I/O57 (io), 69 I/O58 (io), 70 I/O59 (io), 72 I/O60 (io), 73 I/O61 (io), 74 I/O62 (io), 75 I/O63 (io), 80 I/O64 (io), 81 I/O65 (io), 82 I/O66 (io), 83 I/O67 (io), 84 I/O68 (io), 85 I/O69 (io), 88 I/O70 (io), 89 I/O71 (io), 90 I/O72 (io), 91 I/O73 (io), 92 I/O74 (io), 93 I/O75 (io), 95 I/O76 (io), 96 I/O77 (io), 98 I/O78 (io), 99 I/O79 (io), 106 I/O80 (io), 107 I/O81 (io), 108 I/O82 (io), 109 I/O83 (io), 111 I/O84 (io), 112 I/O85 (io), 113 I/O86 (io), 114 I/O87 (io), 116 I/O88 (io), 117 I/O89 (io), 119 I/O90 (io), 120 I/O91 (io), 121 I/O92 (io), 122 I/O93 (io), 123 I/O94 (io), 124 I/O95 (io), 129 I/O0 (io), 130 I/O1 (io), 131 I/O2 (io), 132 I/O3 (io), 133 I/O4 (io), 134 I/O5 (io), 136 I/O6 (io), 137 I/O7 (io), 139 I/O8 (io), 140 I/O9 (io), 141 I/O10 (io), 142 I/O11 (io), 144 I/O12 (io)
part B pins: 4 VCC (power), 5 TDI (in), 6 I5 (in), 7 GND (power), 8 I0/CLK0 (in), 9 I1/CLK1 (in), 12 VCC (power), 15 GND (power), 22 VCC (power), 23 GND (power), 30 GND (power), 31 TMS (in), 32 TCK (in), 33 VCC (power), 38 GND (power), 43 VCC (power), 46 GND (power), 53 VCC (power), 54 GND (power), 55 GND (power), 56 VCC (power), 63 GND (power), 66 VCC (power), 71 GND (power), 76 VCC (power), 77 ENABLE (in), 78 I2 (in), 79 GND (power), 86 GND (power), 87 VCC (power), 94 GND (power), 97 VCC (power), 100 I3/CLK2 (in), 101 I4/CLK3 (in), 102 GND (power), 103 TRST (in), 104 TDO (out), 105 VCC (power), 110 GND (power), 115 VCC (power), 118 GND (power), 125 VCC (power), 126 GND (power), 127 GND (power), 128 VCC (power), 135 GND (power), 138 VCC (power), 143 GND (power)

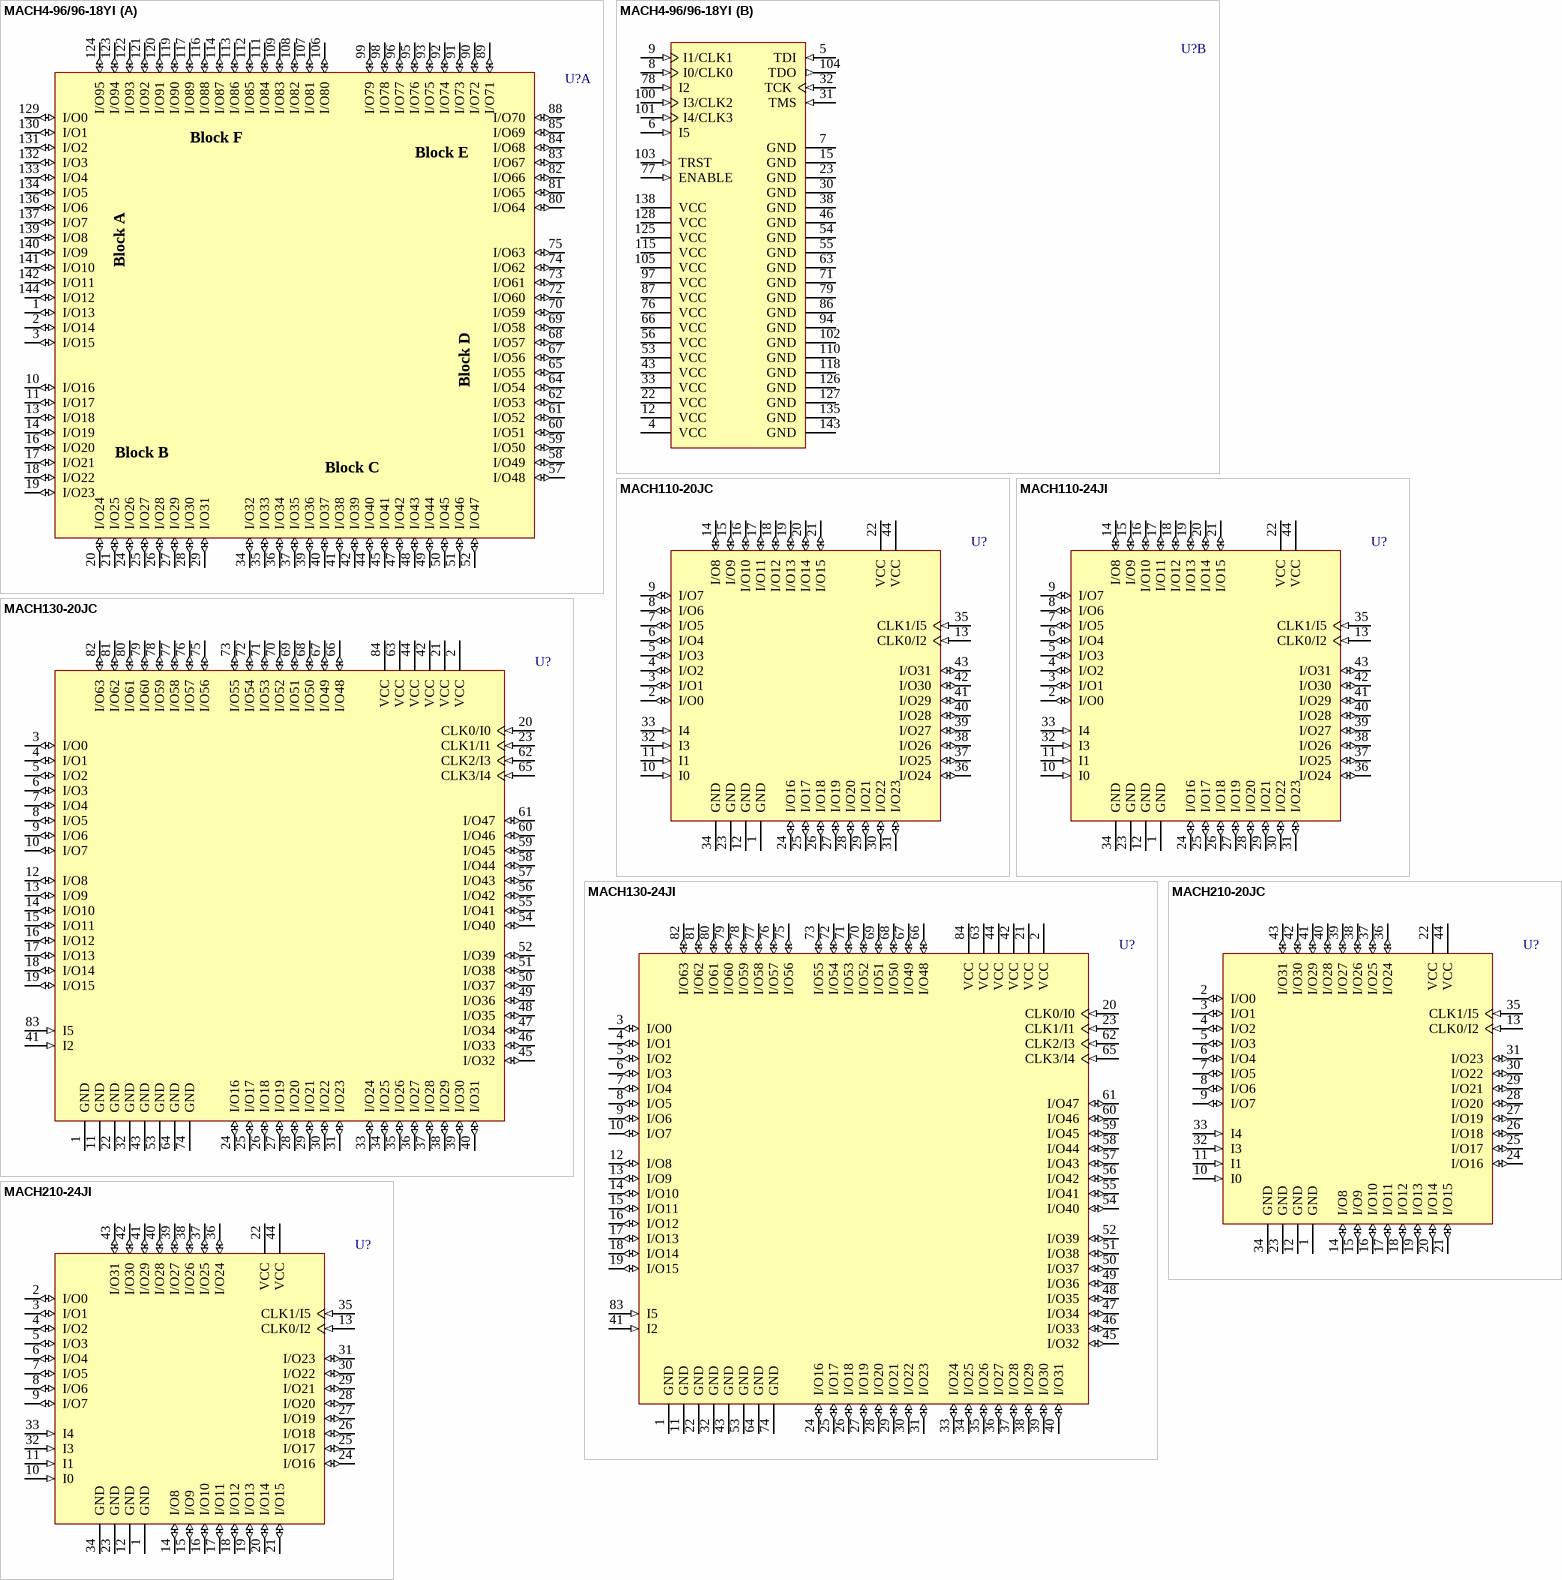
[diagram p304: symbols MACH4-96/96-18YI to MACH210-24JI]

## MACH4-96/96-18YI
designator U?
High-Performance EE CMOS Programmable Logic
footprint PQFP144_N (QFP, 144-Leads, Body 28 x 28mm, Pitch 0.65mm, IPC Medium Density)
footprint PQFP144_L (QFP, 144-Leads, Body 28 x 28mm, Pitch 0.65mm, IPC High Density)
footprint PQFP144_M (QFP, 144-Leads, Body 28 x 28mm, Pitch 0.65mm, IPC Low Density)
3D model MACH4-96-PQFP144 (144-Pin Quad Flat Pack 0.65 mm Pitch)
part A pins: 1 I/O13 (io), 2 I/O14 (io), 3 I/O15 (io), 10 I/O16 (io), 11 I/O17 (io), 13 I/O18 (io), 14 I/O19 (io), 16 I/O20 (io), 17 I/O21 (io), 18 I/O22 (io), 19 I/O23 (io), 20 I/O24 (io), 21 I/O25 (io), 24 I/O26 (io), 25 I/O27 (io), 26 I/O28 (io), 27 I/O29 (io), 28 I/O30 (io), 29 I/O31 (io), 34 I/O32 (io), 35 I/O33 (io), 36 I/O34 (io), 37 I/O35 (io), 39 I/O36 (io), 40 I/O37 (io), 41 I/O38 (io), 42 I/O39 (io), 44 I/O40 (io), 45 I/O41 (io), 47 I/O42 (io), 48 I/O43 (io), 49 I/O44 (io), 50 I/O45 (io), 51 I/O46 (io), 52 I/O47 (io), 57 I/O48 (io), 58 I/O49 (io), 59 I/O50 (io), 60 I/O51 (io), 61 I/O52 (io), 62 I/O53 (io), 64 I/O54 (io), 65 I/O55 (io), 67 I/O56 (io), 68 I/O57 (io), 69 I/O58 (io), 70 I/O59 (io), 72 I/O60 (io), 73 I/O61 (io), 74 I/O62 (io), 75 I/O63 (io), 80 I/O64 (io), 81 I/O65 (io), 82 I/O66 (io), 83 I/O67 (io), 84 I/O68 (io), 85 I/O69 (io), 88 I/O70 (io), 89 I/O71 (io), 90 I/O72 (io), 91 I/O73 (io), 92 I/O74 (io), 93 I/O75 (io), 95 I/O76 (io), 96 I/O77 (io), 98 I/O78 (io), 99 I/O79 (io), 106 I/O80 (io), 107 I/O81 (io), 108 I/O82 (io), 109 I/O83 (io), 111 I/O84 (io), 112 I/O85 (io), 113 I/O86 (io), 114 I/O87 (io), 116 I/O88 (io), 117 I/O89 (io), 119 I/O90 (io), 120 I/O91 (io), 121 I/O92 (io), 122 I/O93 (io), 123 I/O94 (io), 124 I/O95 (io), 129 I/O0 (io), 130 I/O1 (io), 131 I/O2 (io), 132 I/O3 (io), 133 I/O4 (io), 134 I/O5 (io), 136 I/O6 (io), 137 I/O7 (io), 139 I/O8 (io), 140 I/O9 (io), 141 I/O10 (io), 142 I/O11 (io), 144 I/O12 (io)
part B pins: 4 VCC (power), 5 TDI (in), 6 I5 (in), 7 GND (power), 8 I0/CLK0 (in), 9 I1/CLK1 (in), 12 VCC (power), 15 GND (power), 22 VCC (power), 23 GND (power), 30 GND (power), 31 TMS (in), 32 TCK (in), 33 VCC (power), 38 GND (power), 43 VCC (power), 46 GND (power), 53 VCC (power), 54 GND (power), 55 GND (power), 56 VCC (power), 63 GND (power), 66 VCC (power), 71 GND (power), 76 VCC (power), 77 ENABLE (in), 78 I2 (in), 79 GND (power), 86 GND (power), 87 VCC (power), 94 GND (power), 97 VCC (power), 100 I3/CLK2 (in), 101 I4/CLK3 (in), 102 GND (power), 103 TRST (in), 104 TDO (out), 105 VCC (power), 110 GND (power), 115 VCC (power), 118 GND (power), 125 VCC (power), 126 GND (power), 127 GND (power), 128 VCC (power), 135 GND (power), 138 VCC (power), 143 GND (power)

## MACH110-20JC
designator U?
High-Density EE CMOS Programmable Logic
footprint PLCC44_N (Leaded Chip Carrier, 44-Leads, Body 16.6x16.6mm, Pitch 1.27mm, IPC Medium Density)
footprint PLCC44_L (Leaded Chip Carrier, 44-Leads, Body 16.6x16.6mm, Pitch 1.27mm, IPC High Density)
footprint PLCC44_M (Leaded Chip Carrier, 44-Leads, Body 16.6x16.6mm, Pitch 1.27mm, IPC Low Density)
3D model MACH110-PLCC44 (44-Pin Leaded Chip Carrier 1.27 mm Pitch)
pins: 1 GND (power), 2 I/O0 (io), 3 I/O1 (io), 4 I/O2 (io), 5 I/O3 (io), 6 I/O4 (io), 7 I/O5 (io), 8 I/O6 (io), 9 I/O7 (io), 10 I0 (in), 11 I1 (in), 12 GND (power), 13 CLK0/I2 (in), 14 I/O8 (io), 15 I/O9 (io), 16 I/O10 (io), 17 I/O11 (io), 18 I/O12 (io), 19 I/O13 (io), 20 I/O14 (io), 21 I/O15 (io), 22 VCC (power), 23 GND (power), 24 I/O16 (io), 25 I/O17 (io), 26 I/O18 (io), 27 I/O19 (io), 28 I/O20 (io), 29 I/O21 (io), 30 I/O22 (io), 31 I/O23 (io), 32 I3 (in), 33 I4 (in), 34 GND (power), 35 CLK1/I5 (in), 36 I/O24 (io), 37 I/O25 (io), 38 I/O26 (io), 39 I/O27 (io), 40 I/O28 (io), 41 I/O29 (io), 42 I/O30 (io), 43 I/O31 (io), 44 VCC (power)

## MACH110-24JI
designator U?
High-Density EE CMOS Programmable Logic
footprint PLCC44_N (Leaded Chip Carrier, 44-Leads, Body 16.6x16.6mm, Pitch 1.27mm, IPC Medium Density)
footprint PLCC44_L (Leaded Chip Carrier, 44-Leads, Body 16.6x16.6mm, Pitch 1.27mm, IPC High Density)
footprint PLCC44_M (Leaded Chip Carrier, 44-Leads, Body 16.6x16.6mm, Pitch 1.27mm, IPC Low Density)
3D model MACH110-PLCC44 (44-Pin Leaded Chip Carrier 1.27 mm Pitch)
pins: 1 GND (power), 2 I/O0 (io), 3 I/O1 (io), 4 I/O2 (io), 5 I/O3 (io), 6 I/O4 (io), 7 I/O5 (io), 8 I/O6 (io), 9 I/O7 (io), 10 I0 (in), 11 I1 (in), 12 GND (power), 13 CLK0/I2 (in), 14 I/O8 (io), 15 I/O9 (io), 16 I/O10 (io), 17 I/O11 (io), 18 I/O12 (io), 19 I/O13 (io), 20 I/O14 (io), 21 I/O15 (io), 22 VCC (power), 23 GND (power), 24 I/O16 (io), 25 I/O17 (io), 26 I/O18 (io), 27 I/O19 (io), 28 I/O20 (io), 29 I/O21 (io), 30 I/O22 (io), 31 I/O23 (io), 32 I3 (in), 33 I4 (in), 34 GND (power), 35 CLK1/I5 (in), 36 I/O24 (io), 37 I/O25 (io), 38 I/O26 (io), 39 I/O27 (io), 40 I/O28 (io), 41 I/O29 (io), 42 I/O30 (io), 43 I/O31 (io), 44 VCC (power)

## MACH130-20JC
designator U?
High-Density EE CMOS Programmable Logic
footprint PLCC84_N (Leaded Chip Carrier, 84-Leads, Body 29.3x29.3mm, Pitch 1.27mm, IPC Medium Density)
footprint PLCC84_L (Leaded Chip Carrier, 84-Leads, Body 29.3x29.3mm, Pitch 1.27mm, IPC High Density)
footprint PLCC84_M (Leaded Chip Carrier, 84-Leads, Body 29.3x29.3mm, Pitch 1.27mm, IPC Low Density)
3D model MACH130-PLCC84 (84-Pin Leaded Chip Carrier 1.27 mm Pitch)
pins: 1 GND (power), 2 VCC (power), 3 I/O0 (io), 4 I/O1 (io), 5 I/O2 (io), 6 I/O3 (io), 7 I/O4 (io), 8 I/O5 (io), 9 I/O6 (io), 10 I/O7 (io), 11 GND (power), 12 I/O8 (io), 13 I/O9 (io), 14 I/O10 (io), 15 I/O11 (io), 16 I/O12 (io), 17 I/O13 (io), 18 I/O14 (io), 19 I/O15 (io), 20 CLK0/I0 (in), 21 VCC (power), 22 GND (power), 23 CLK1/I1 (in), 24 I/O16 (io), 25 I/O17 (io), 26 I/O18 (io), 27 I/O19 (io), 28 I/O20 (io), 29 I/O21 (io), 30 I/O22 (io), 31 I/O23 (io), 32 GND (power), 33 I/O24 (io), 34 I/O25 (io), 35 I/O26 (io), 36 I/O27 (io), 37 I/O28 (io), 38 I/O29 (io), 39 I/O30 (io), 40 I/O31 (io), 41 I2 (in), 42 VCC (power), 43 GND (power), 44 VCC (power), 45 I/O32 (io), 46 I/O33 (io), 47 I/O34 (io), 48 I/O35 (io), 49 I/O36 (io), 50 I/O37 (io), 51 I/O38 (io), 52 I/O39 (io), 53 GND (power), 54 I/O40 (io), 55 I/O41 (io), 56 I/O42 (io), 57 I/O43 (io), 58 I/O44 (io), 59 I/O45 (io), 60 I/O46 (io), 61 I/O47 (io), 62 CLK2/I3 (in), 63 VCC (power), 64 GND (power), 65 CLK3/I4 (in), 66 I/O48 (io), 67 I/O49 (io), 68 I/O50 (io), 69 I/O51 (io), 70 I/O52 (io), 71 I/O53 (io), 72 I/O54 (io), 73 I/O55 (io), 74 GND (power), 75 I/O56 (io), 76 I/O57 (io), 77 I/O58 (io), 78 I/O59 (io), 79 I/O60 (io), 80 I/O61 (io), 81 I/O62 (io), 82 I/O63 (io), 83 I5 (in), 84 VCC (power)

## MACH130-24JI
designator U?
High-Density EE CMOS Programmable Logic
footprint PLCC84_N (Leaded Chip Carrier, 84-Leads, Body 29.3x29.3mm, Pitch 1.27mm, IPC Medium Density)
footprint PLCC84_L (Leaded Chip Carrier, 84-Leads, Body 29.3x29.3mm, Pitch 1.27mm, IPC High Density)
footprint PLCC84_M (Leaded Chip Carrier, 84-Leads, Body 29.3x29.3mm, Pitch 1.27mm, IPC Low Density)
3D model MACH130-PLCC84 (84-Pin Leaded Chip Carrier 1.27 mm Pitch)
pins: 1 GND (power), 2 VCC (power), 3 I/O0 (io), 4 I/O1 (io), 5 I/O2 (io), 6 I/O3 (io), 7 I/O4 (io), 8 I/O5 (io), 9 I/O6 (io), 10 I/O7 (io), 11 GND (power), 12 I/O8 (io), 13 I/O9 (io), 14 I/O10 (io), 15 I/O11 (io), 16 I/O12 (io), 17 I/O13 (io), 18 I/O14 (io), 19 I/O15 (io), 20 CLK0/I0 (in), 21 VCC (power), 22 GND (power), 23 CLK1/I1 (in), 24 I/O16 (io), 25 I/O17 (io), 26 I/O18 (io), 27 I/O19 (io), 28 I/O20 (io), 29 I/O21 (io), 30 I/O22 (io), 31 I/O23 (io), 32 GND (power), 33 I/O24 (io), 34 I/O25 (io), 35 I/O26 (io), 36 I/O27 (io), 37 I/O28 (io), 38 I/O29 (io), 39 I/O30 (io), 40 I/O31 (io), 41 I2 (in), 42 VCC (power), 43 GND (power), 44 VCC (power), 45 I/O32 (io), 46 I/O33 (io), 47 I/O34 (io), 48 I/O35 (io), 49 I/O36 (io), 50 I/O37 (io), 51 I/O38 (io), 52 I/O39 (io), 53 GND (power), 54 I/O40 (io), 55 I/O41 (io), 56 I/O42 (io), 57 I/O43 (io), 58 I/O44 (io), 59 I/O45 (io), 60 I/O46 (io), 61 I/O47 (io), 62 CLK2/I3 (in), 63 VCC (power), 64 GND (power), 65 CLK3/I4 (in), 66 I/O48 (io), 67 I/O49 (io), 68 I/O50 (io), 69 I/O51 (io), 70 I/O52 (io), 71 I/O53 (io), 72 I/O54 (io), 73 I/O55 (io), 74 GND (power), 75 I/O56 (io), 76 I/O57 (io), 77 I/O58 (io), 78 I/O59 (io), 79 I/O60 (io), 80 I/O61 (io), 81 I/O62 (io), 82 I/O63 (io), 83 I5 (in), 84 VCC (power)

## MACH210-20JC
designator U?
High-Density EE CMOS Programmable Logic
footprint PLCC44_N (Leaded Chip Carrier, 44-Leads, Body 16.6x16.6mm, Pitch 1.27mm, IPC Medium Density)
footprint PLCC44_L (Leaded Chip Carrier, 44-Leads, Body 16.6x16.6mm, Pitch 1.27mm, IPC High Density)
footprint PLCC44_M (Leaded Chip Carrier, 44-Leads, Body 16.6x16.6mm, Pitch 1.27mm, IPC Low Density)
3D model MACH210-PLCC44 (44-Pin Leaded Chip Carrier 1.27 mm Pitch)
pins: 1 GND (power), 2 I/O0 (io), 3 I/O1 (io), 4 I/O2 (io), 5 I/O3 (io), 6 I/O4 (io), 7 I/O5 (io), 8 I/O6 (io), 9 I/O7 (io), 10 I0 (in), 11 I1 (in), 12 GND (power), 13 CLK0/I2 (in), 14 I/O8 (io), 15 I/O9 (io), 16 I/O10 (io), 17 I/O11 (io), 18 I/O12 (io), 19 I/O13 (io), 20 I/O14 (io), 21 I/O15 (io), 22 VCC (power), 23 GND (power), 24 I/O16 (io), 25 I/O17 (io), 26 I/O18 (io), 27 I/O19 (io), 28 I/O20 (io), 29 I/O21 (io), 30 I/O22 (io), 31 I/O23 (io), 32 I3 (in), 33 I4 (in), 34 GND (power), 35 CLK1/I5 (in), 36 I/O24 (io), 37 I/O25 (io), 38 I/O26 (io), 39 I/O27 (io), 40 I/O28 (io), 41 I/O29 (io), 42 I/O30 (io), 43 I/O31 (io), 44 VCC (power)

## MACH210-24JI
designator U?
High-Density EE CMOS Programmable Logic
footprint PLCC44_N (Leaded Chip Carrier, 44-Leads, Body 16.6x16.6mm, Pitch 1.27mm, IPC Medium Density)
footprint PLCC44_L (Leaded Chip Carrier, 44-Leads, Body 16.6x16.6mm, Pitch 1.27mm, IPC High Density)
footprint PLCC44_M (Leaded Chip Carrier, 44-Leads, Body 16.6x16.6mm, Pitch 1.27mm, IPC Low Density)
3D model MACH210-PLCC44 (44-Pin Leaded Chip Carrier 1.27 mm Pitch)
pins: 1 GND (power), 2 I/O0 (io), 3 I/O1 (io), 4 I/O2 (io), 5 I/O3 (io), 6 I/O4 (io), 7 I/O5 (io), 8 I/O6 (io), 9 I/O7 (io), 10 I0 (in), 11 I1 (in), 12 GND (power), 13 CLK0/I2 (in), 14 I/O8 (io), 15 I/O9 (io), 16 I/O10 (io), 17 I/O11 (io), 18 I/O12 (io), 19 I/O13 (io), 20 I/O14 (io), 21 I/O15 (io), 22 VCC (power), 23 GND (power), 24 I/O16 (io), 25 I/O17 (io), 26 I/O18 (io), 27 I/O19 (io), 28 I/O20 (io), 29 I/O21 (io), 30 I/O22 (io), 31 I/O23 (io), 32 I3 (in), 33 I4 (in), 34 GND (power), 35 CLK1/I5 (in), 36 I/O24 (io), 37 I/O25 (io), 38 I/O26 (io), 39 I/O27 (io), 40 I/O28 (io), 41 I/O29 (io), 42 I/O30 (io), 43 I/O31 (io), 44 VCC (power)

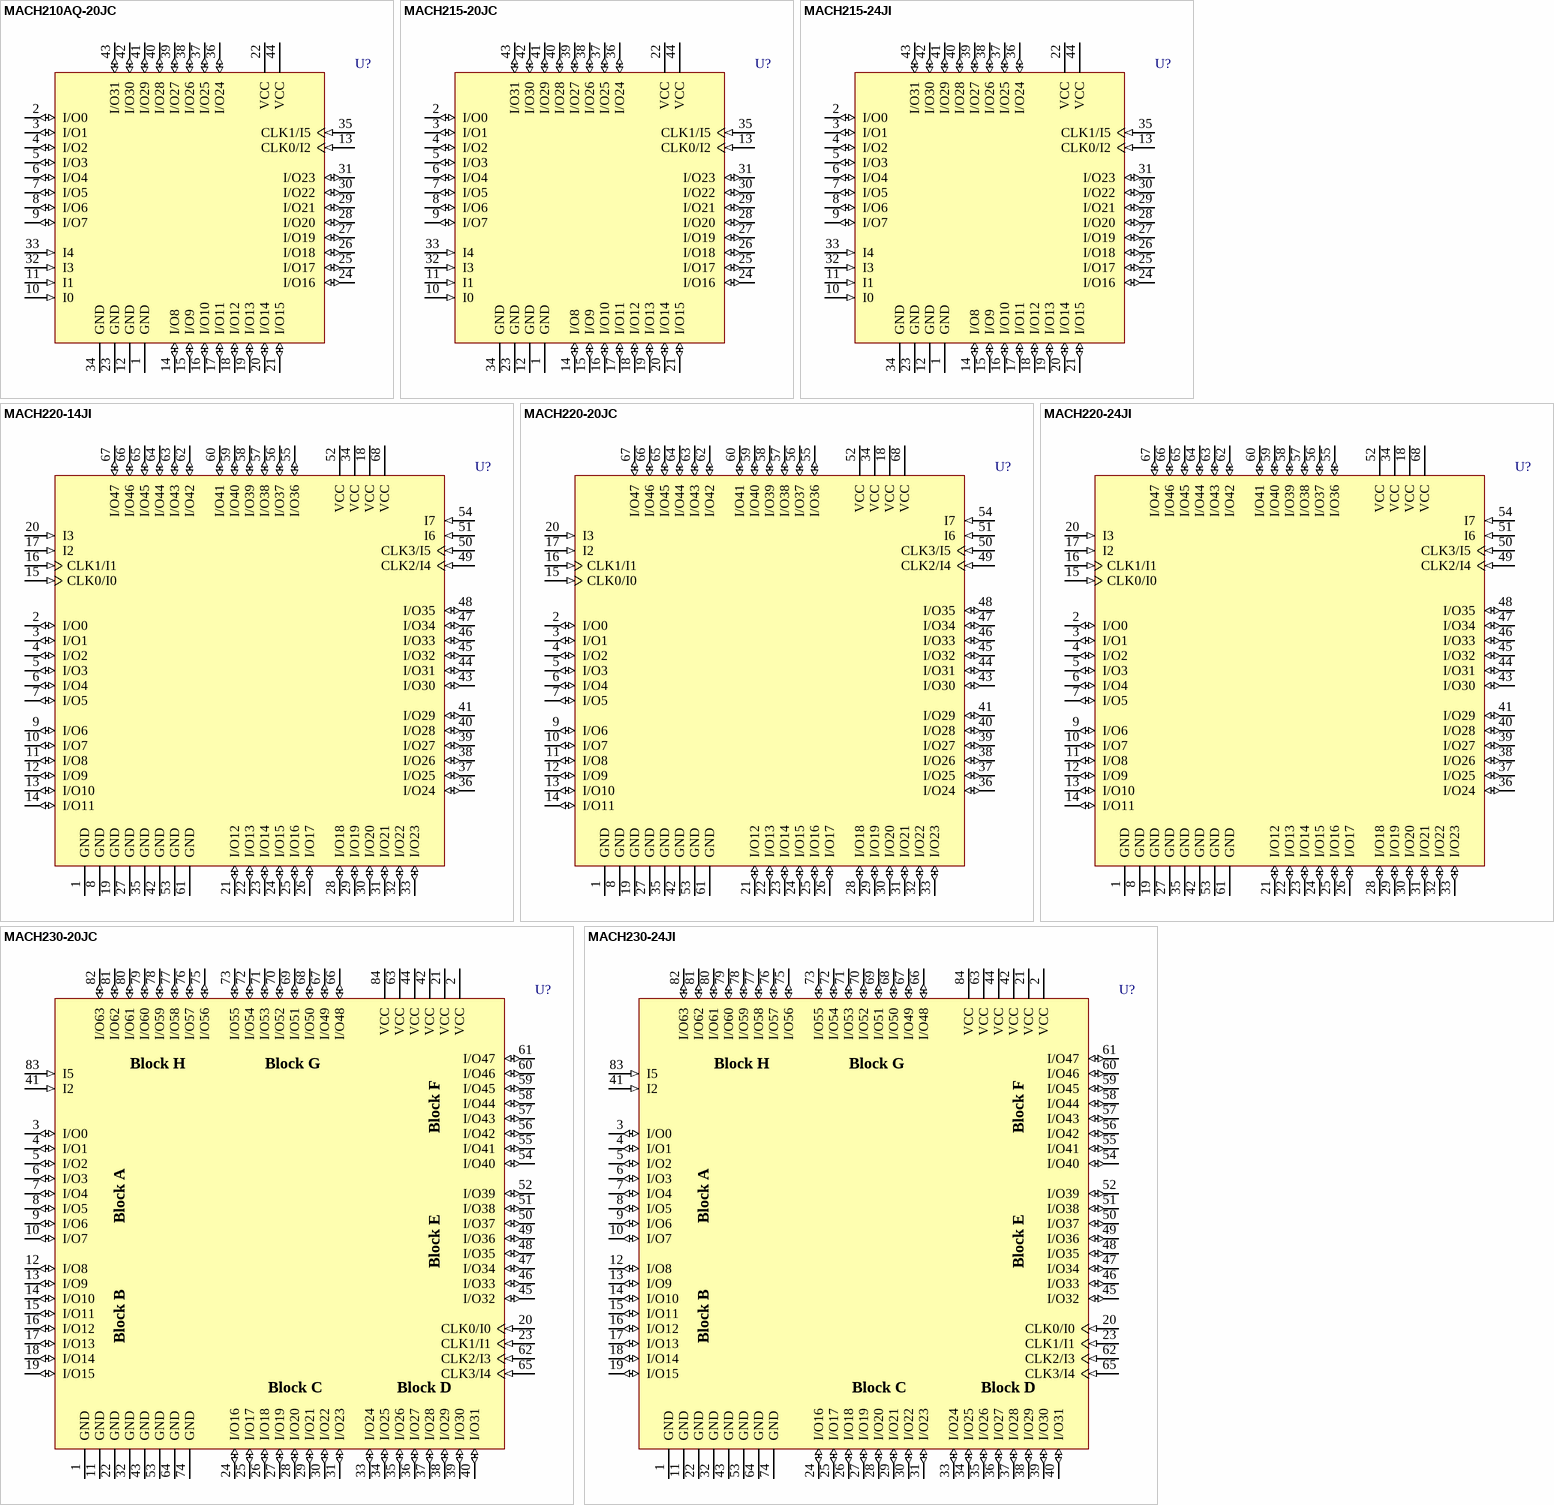
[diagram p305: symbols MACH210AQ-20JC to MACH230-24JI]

## MACH210AQ-20JC
designator U?
High-Density EE CMOS Programmable Logic
footprint PLCC44_N (Leaded Chip Carrier, 44-Leads, Body 16.6x16.6mm, Pitch 1.27mm, IPC Medium Density)
footprint PLCC44_L (Leaded Chip Carrier, 44-Leads, Body 16.6x16.6mm, Pitch 1.27mm, IPC High Density)
footprint PLCC44_M (Leaded Chip Carrier, 44-Leads, Body 16.6x16.6mm, Pitch 1.27mm, IPC Low Density)
3D model MACH210AQ-PLCC44 (44-Pin Leaded Chip Carrier 1.27 mm Pitch)
pins: 1 GND (power), 2 I/O0 (io), 3 I/O1 (io), 4 I/O2 (io), 5 I/O3 (io), 6 I/O4 (io), 7 I/O5 (io), 8 I/O6 (io), 9 I/O7 (io), 10 I0 (in), 11 I1 (in), 12 GND (power), 13 CLK0/I2 (in), 14 I/O8 (io), 15 I/O9 (io), 16 I/O10 (io), 17 I/O11 (io), 18 I/O12 (io), 19 I/O13 (io), 20 I/O14 (io), 21 I/O15 (io), 22 VCC (power), 23 GND (power), 24 I/O16 (io), 25 I/O17 (io), 26 I/O18 (io), 27 I/O19 (io), 28 I/O20 (io), 29 I/O21 (io), 30 I/O22 (io), 31 I/O23 (io), 32 I3 (in), 33 I4 (in), 34 GND (power), 35 CLK1/I5 (in), 36 I/O24 (io), 37 I/O25 (io), 38 I/O26 (io), 39 I/O27 (io), 40 I/O28 (io), 41 I/O29 (io), 42 I/O30 (io), 43 I/O31 (io), 44 VCC (power)

## MACH215-20JC
designator U?
High-Density EE CMOS Programmable Logic
footprint PLCC44_N (Leaded Chip Carrier, 44-Leads, Body 16.6x16.6mm, Pitch 1.27mm, IPC Medium Density)
footprint PLCC44_L (Leaded Chip Carrier, 44-Leads, Body 16.6x16.6mm, Pitch 1.27mm, IPC High Density)
footprint PLCC44_M (Leaded Chip Carrier, 44-Leads, Body 16.6x16.6mm, Pitch 1.27mm, IPC Low Density)
3D model MACH215-PLCC44 (44-Pin Leaded Chip Carrier 1.27 mm Pitch)
pins: 1 GND (power), 2 I/O0 (io), 3 I/O1 (io), 4 I/O2 (io), 5 I/O3 (io), 6 I/O4 (io), 7 I/O5 (io), 8 I/O6 (io), 9 I/O7 (io), 10 I0 (in), 11 I1 (in), 12 GND (power), 13 CLK0/I2 (in), 14 I/O8 (io), 15 I/O9 (io), 16 I/O10 (io), 17 I/O11 (io), 18 I/O12 (io), 19 I/O13 (io), 20 I/O14 (io), 21 I/O15 (io), 22 VCC (power), 23 GND (power), 24 I/O16 (io), 25 I/O17 (io), 26 I/O18 (io), 27 I/O19 (io), 28 I/O20 (io), 29 I/O21 (io), 30 I/O22 (io), 31 I/O23 (io), 32 I3 (in), 33 I4 (in), 34 GND (power), 35 CLK1/I5 (in), 36 I/O24 (io), 37 I/O25 (io), 38 I/O26 (io), 39 I/O27 (io), 40 I/O28 (io), 41 I/O29 (io), 42 I/O30 (io), 43 I/O31 (io), 44 VCC (power)

## MACH215-24JI
designator U?
High-Density EE CMOS Programmable Logic
footprint PLCC44_N (Leaded Chip Carrier, 44-Leads, Body 16.6x16.6mm, Pitch 1.27mm, IPC Medium Density)
footprint PLCC44_L (Leaded Chip Carrier, 44-Leads, Body 16.6x16.6mm, Pitch 1.27mm, IPC High Density)
footprint PLCC44_M (Leaded Chip Carrier, 44-Leads, Body 16.6x16.6mm, Pitch 1.27mm, IPC Low Density)
3D model MACH215-PLCC44 (44-Pin Leaded Chip Carrier 1.27 mm Pitch)
pins: 1 GND (power), 2 I/O0 (io), 3 I/O1 (io), 4 I/O2 (io), 5 I/O3 (io), 6 I/O4 (io), 7 I/O5 (io), 8 I/O6 (io), 9 I/O7 (io), 10 I0 (in), 11 I1 (in), 12 GND (power), 13 CLK0/I2 (in), 14 I/O8 (io), 15 I/O9 (io), 16 I/O10 (io), 17 I/O11 (io), 18 I/O12 (io), 19 I/O13 (io), 20 I/O14 (io), 21 I/O15 (io), 22 VCC (power), 23 GND (power), 24 I/O16 (io), 25 I/O17 (io), 26 I/O18 (io), 27 I/O19 (io), 28 I/O20 (io), 29 I/O21 (io), 30 I/O22 (io), 31 I/O23 (io), 32 I3 (in), 33 I4 (in), 34 GND (power), 35 CLK1/I5 (in), 36 I/O24 (io), 37 I/O25 (io), 38 I/O26 (io), 39 I/O27 (io), 40 I/O28 (io), 41 I/O29 (io), 42 I/O30 (io), 43 I/O31 (io), 44 VCC (power)

## MACH220-14JI
designator U?
High-Density EE CMOS Programmable Logic
footprint PLCC68_N (Leaded Chip Carrier, 68-Leads, Body 24x24mm, Pitch 1.27mm, IPC Medium Density)
footprint PLCC68_L (Leaded Chip Carrier, 68-Leads, Body 24x24mm, Pitch 1.27mm, IPC High Density)
footprint PLCC68_M (Leaded Chip Carrier, 68-Leads, Body 24x24mm, Pitch 1.27mm, IPC Low Density)
3D model MACH220-PLCC68 (68-Pin Leaded Chip Carrier 1.27 mm Pitch)
pins: 1 GND (power), 2 I/O0 (io), 3 I/O1 (io), 4 I/O2 (io), 5 I/O3 (io), 6 I/O4 (io), 7 I/O5 (io), 8 GND (power), 9 I/O6 (io), 10 I/O7 (io), 11 I/O8 (io), 12 I/O9 (io), 13 I/O10 (io), 14 I/O11 (io), 15 CLK0/I0 (in), 16 CLK1/I1 (in), 17 I2 (in), 18 VCC (power), 19 GND (power), 20 I3 (in), 21 I/O12 (io), 22 I/O13 (io), 23 I/O14 (io), 24 I/O15 (io), 25 I/O16 (io), 26 I/O17 (io), 27 GND (power), 28 I/O18 (io), 29 I/O19 (io), 30 I/O20 (io), 31 I/O21 (io), 32 I/O22 (io), 33 I/O23 (io), 34 VCC (power), 35 GND (power), 36 I/O24 (io), 37 I/O25 (io), 38 I/O26 (io), 39 I/O27 (io), 40 I/O28 (io), 41 I/O29 (io), 42 GND (power), 43 I/O30 (io), 44 I/O31 (io), 45 I/O32 (io), 46 I/O33 (io), 47 I/O34 (io), 48 I/O35 (io), 49 CLK2/I4 (in), 50 CLK3/I5 (in), 51 I6 (in), 52 VCC (power), 53 GND (power), 54 I7 (in), 55 I/O36 (io), 56 I/O37 (io), 57 I/O38 (io), 58 I/O39 (io), 59 I/O40 (io), 60 I/O41 (io), 61 GND (power), 62 I/O42 (io), 63 I/O43 (io), 64 I/O44 (io), 65 I/O45 (io), 66 I/O46 (io), 67 I/O47 (io), 68 VCC (power)

## MACH220-20JC
designator U?
High-Density EE CMOS Programmable Logic
footprint PLCC68_N (Leaded Chip Carrier, 68-Leads, Body 24x24mm, Pitch 1.27mm, IPC Medium Density)
footprint PLCC68_L (Leaded Chip Carrier, 68-Leads, Body 24x24mm, Pitch 1.27mm, IPC High Density)
footprint PLCC68_M (Leaded Chip Carrier, 68-Leads, Body 24x24mm, Pitch 1.27mm, IPC Low Density)
3D model MACH220-PLCC68 (68-Pin Leaded Chip Carrier 1.27 mm Pitch)
pins: 1 GND (power), 2 I/O0 (io), 3 I/O1 (io), 4 I/O2 (io), 5 I/O3 (io), 6 I/O4 (io), 7 I/O5 (io), 8 GND (power), 9 I/O6 (io), 10 I/O7 (io), 11 I/O8 (io), 12 I/O9 (io), 13 I/O10 (io), 14 I/O11 (io), 15 CLK0/I0 (in), 16 CLK1/I1 (in), 17 I2 (in), 18 VCC (power), 19 GND (power), 20 I3 (in), 21 I/O12 (io), 22 I/O13 (io), 23 I/O14 (io), 24 I/O15 (io), 25 I/O16 (io), 26 I/O17 (io), 27 GND (power), 28 I/O18 (io), 29 I/O19 (io), 30 I/O20 (io), 31 I/O21 (io), 32 I/O22 (io), 33 I/O23 (io), 34 VCC (power), 35 GND (power), 36 I/O24 (io), 37 I/O25 (io), 38 I/O26 (io), 39 I/O27 (io), 40 I/O28 (io), 41 I/O29 (io), 42 GND (power), 43 I/O30 (io), 44 I/O31 (io), 45 I/O32 (io), 46 I/O33 (io), 47 I/O34 (io), 48 I/O35 (io), 49 CLK2/I4 (in), 50 CLK3/I5 (in), 51 I6 (in), 52 VCC (power), 53 GND (power), 54 I7 (in), 55 I/O36 (io), 56 I/O37 (io), 57 I/O38 (io), 58 I/O39 (io), 59 I/O40 (io), 60 I/O41 (io), 61 GND (power), 62 I/O42 (io), 63 I/O43 (io), 64 I/O44 (io), 65 I/O45 (io), 66 I/O46 (io), 67 I/O47 (io), 68 VCC (power)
